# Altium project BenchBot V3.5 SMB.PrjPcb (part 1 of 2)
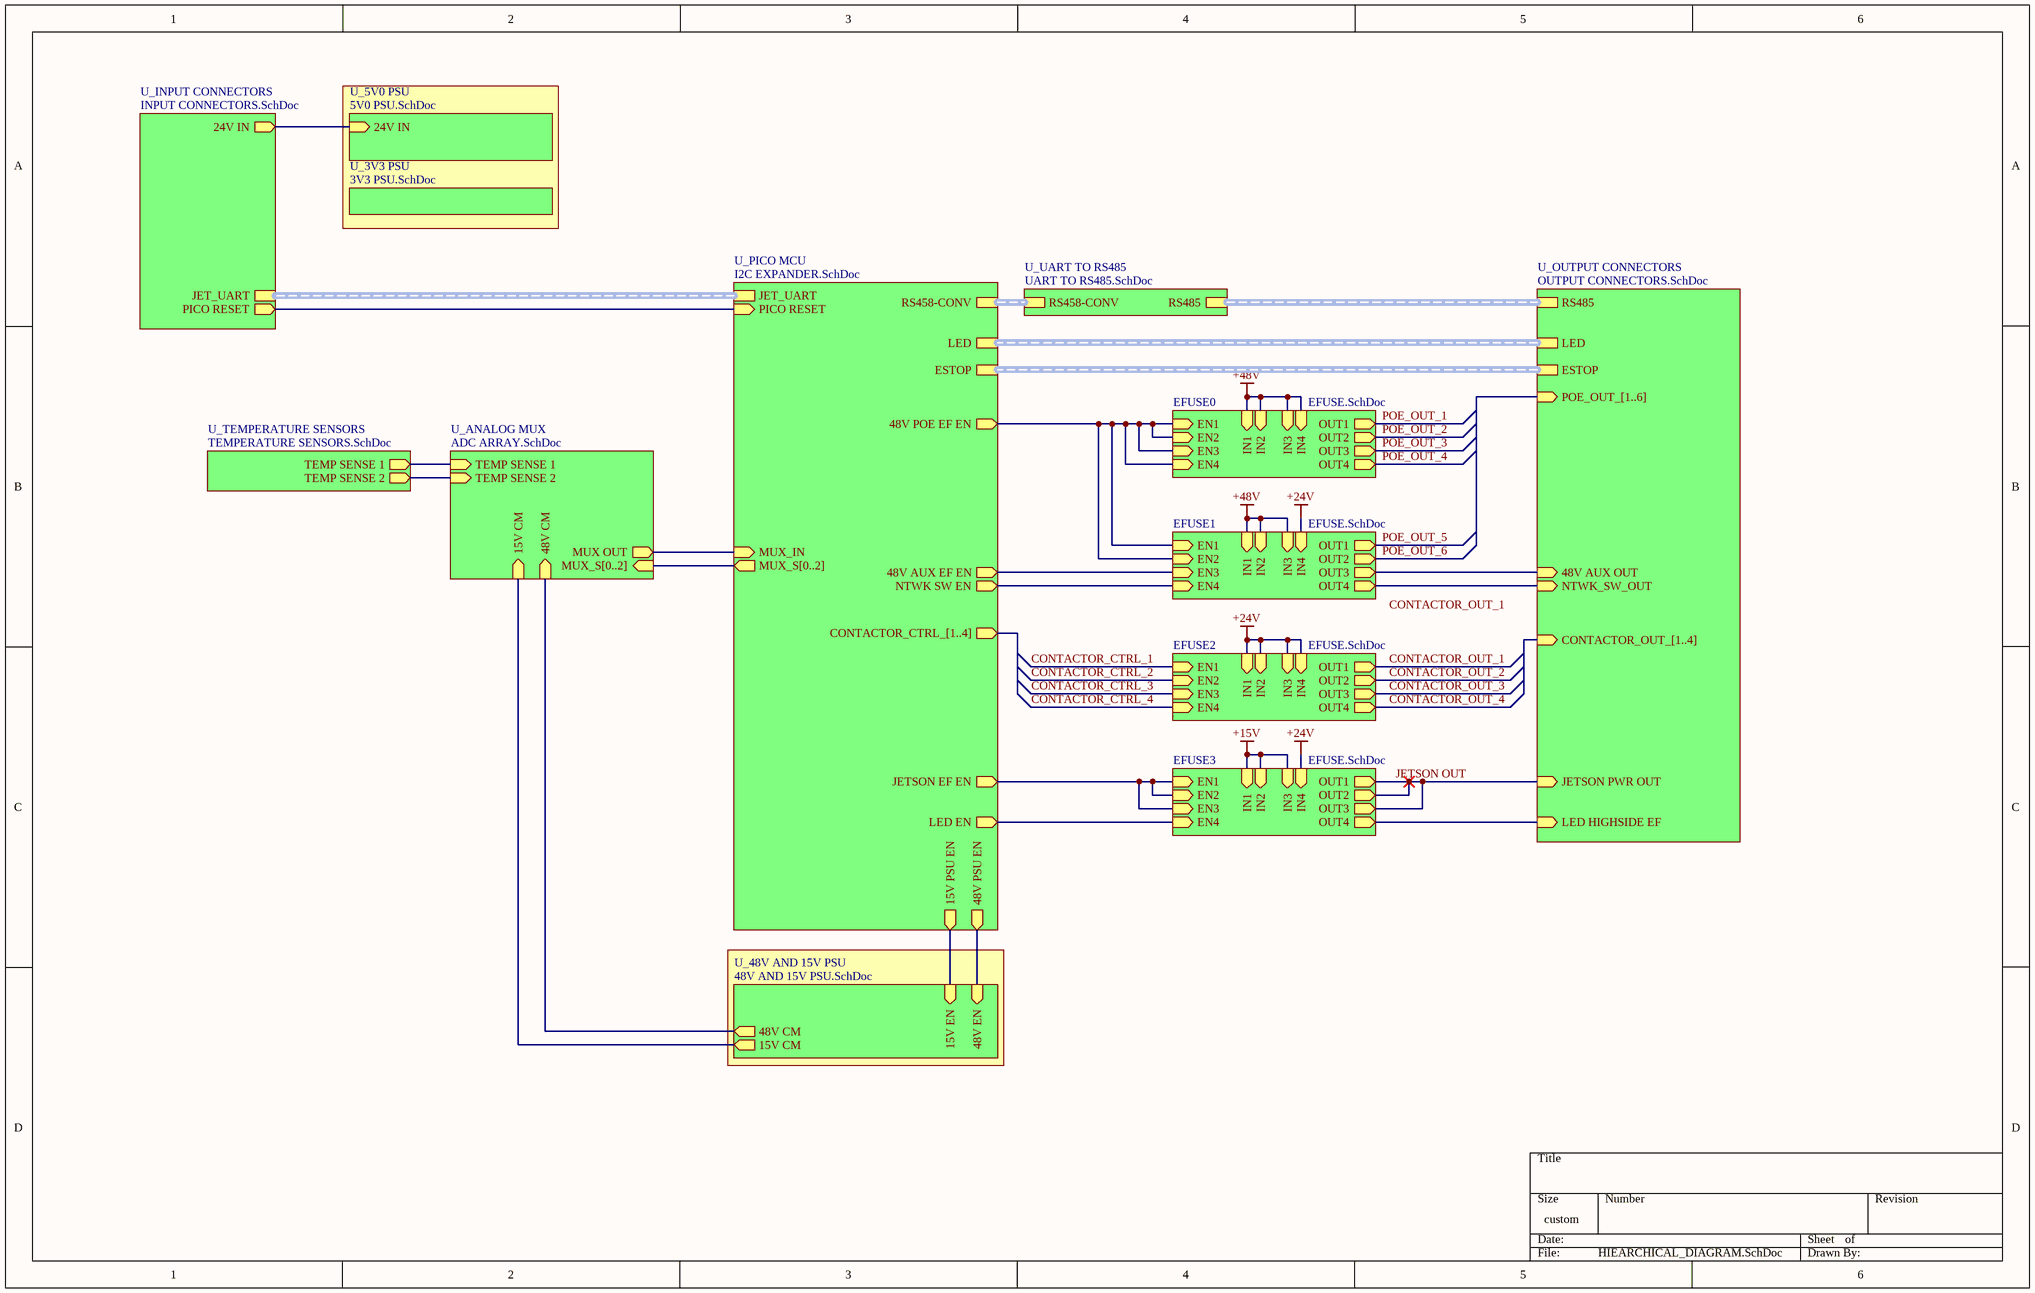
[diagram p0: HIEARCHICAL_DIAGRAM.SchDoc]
13 sheets, 242 parts. Net scope: hierarchical (ports join the sheet entries above them; power ports are global).
Board file: System Management Board.PcbDoc
Sheets:
  HIEARCHICAL_DIAGRAM.SchDoc
    U_3V3 PSU = 3V3 PSU.SchDoc
    U_5V0 PSU = 5V0 PSU.SchDoc
    U_ANALOG MUX = ADC ARRAY.SchDoc
    EFUSE0 = EFUSE.SchDoc
    U_INPUT CONNECTORS = INPUT CONNECTORS.SchDoc
    U_OUTPUT CONNECTORS = OUTPUT CONNECTORS.SchDoc
    U_PICO MCU = I2C EXPANDER.SchDoc
    U_TEMPERATURE SENSORS = TEMPERATURE SENSORS.SchDoc
    U_UART TO RS485 = UART TO RS485.SchDoc
    U_48V AND 15V PSU = 48V AND 15V PSU.SchDoc
    EFUSE1 = EFUSE.SchDoc
    EFUSE2 = EFUSE.SchDoc
    EFUSE3 = EFUSE.SchDoc
  MECHANICAL.SchDoc
  ADC.SchDoc

## Sheet HIEARCHICAL_DIAGRAM.SchDoc
size 381 x 241 mm

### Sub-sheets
EFUSE0 = EFUSE.SchDoc: OUT1 (out), EN1 (in), IN1 (in), IN2 (in), IN3 (in), IN4 (in), OUT2 (out), OUT3 (out), OUT4 (out), EN2 (in), EN3 (in), EN4 (in)
EFUSE1 = EFUSE.SchDoc: OUT1 (out), EN1 (in), IN1 (in), IN2 (in), IN3 (in), IN4 (in), OUT2 (out), OUT3 (out), OUT4 (out), EN2 (in), EN3 (in), EN4 (in)
EFUSE2 = EFUSE.SchDoc: OUT1 (out), EN1 (in), IN1 (in), IN2 (in), IN3 (in), IN4 (in), OUT2 (out), OUT3 (out), OUT4 (out), EN2 (in), EN3 (in), EN4 (in)
EFUSE3 = EFUSE.SchDoc: OUT1 (out), EN1 (in), IN1 (in), IN2 (in), IN3 (in), IN4 (in), OUT2 (out), OUT3 (out), OUT4 (out), EN2 (in), EN3 (in), EN4 (in)
U_3V3 PSU = 3V3 PSU.SchDoc: no entries
U_5V0 PSU = 5V0 PSU.SchDoc: 24V IN (in)
U_48V AND 15V PSU = 48V AND 15V PSU.SchDoc: 48V CM (out), 15V CM (out), 15V EN (in), 48V EN (in)
U_ANALOG MUX = ADC ARRAY.SchDoc: MUX OUT (out), TEMP SENSE 2 (in), TEMP SENSE 1 (in), 48V CM (in), 15V CM (in), MUX_S[0..2] (in)
U_INPUT CONNECTORS = INPUT CONNECTORS.SchDoc: PICO RESET (out), JET_UART (harness UART0), 24V IN (out)
U_OUTPUT CONNECTORS = OUTPUT CONNECTORS.SchDoc: NTWK_SW_OUT (in), JETSON PWR OUT (in), 48V AUX OUT (in), RS485 (harness RS485), LED HIGHSIDE EF (in), CONTACTOR_OUT_[1..4] (in), ESTOP (harness ESTOP_CONN), LED (harness LED), POE_OUT_[1..6] (in)
U_PICO MCU = I2C EXPANDER.SchDoc: NTWK SW EN (out), LED EN (out), ESTOP (harness ESTOP_CONN), JETSON EF EN (out), 15V PSU EN (out), 48V PSU EN (out), RS458-CONV (harness RS485 CONVERSION), JET_UART (harness UART0), CONTACTOR_CTRL_[1..4] (out), PICO RESET (in), MUX_S[0..2] (out), MUX_IN (in), 48V AUX EF EN (out), LED (harness LED), 48V POE EF EN (out)
U_TEMPERATURE SENSORS = TEMPERATURE SENSORS.SchDoc: TEMP SENSE 1 (out), TEMP SENSE 2 (out)
U_UART TO RS485 = UART TO RS485.SchDoc: RS485 (harness RS485), RS458-CONV (harness RS485 CONVERSION)

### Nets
+15V: sheet EFUSE3/IN1, sheet EFUSE3/IN2, sheet EFUSE3/IN3
+24V: sheet EFUSE1/IN4, sheet EFUSE2/IN1, sheet EFUSE2/IN2, sheet EFUSE2/IN3, sheet EFUSE2/IN4, sheet EFUSE3/IN4
+48V: sheet EFUSE0/IN1, sheet EFUSE0/IN2, sheet EFUSE0/IN3, sheet EFUSE0/IN4, sheet EFUSE1/IN1, sheet EFUSE1/IN2, sheet EFUSE1/IN3
15V CM: sheet U_ANALOG MUX/15V CM, sheet U_48V AND 15V PSU/15V CM
48V POE EF EN: sheet EFUSE0/EN1, sheet EFUSE0/EN2, sheet EFUSE0/EN3, sheet EFUSE0/EN4, sheet U_PICO MCU/48V POE EF EN, sheet EFUSE1/EN1, sheet EFUSE1/EN2
48V_AUX_EF_EN: sheet U_PICO MCU/48V AUX EF EN, sheet EFUSE1/EN3
+24_VIN: sheet U_5V0 PSU/24V IN, sheet U_INPUT CONNECTORS/24V IN
~{+15_PWR_EN}: sheet U_PICO MCU/15V PSU EN, sheet U_48V AND 15V PSU/15V EN
~{+48_PWR_EN}: sheet U_PICO MCU/48V PSU EN, sheet U_48V AND 15V PSU/48V EN
EN1: sheet U_PICO MCU/JETSON EF EN, sheet EFUSE3/EN1, sheet EFUSE3/EN2, sheet EFUSE3/EN3
EN4: sheet U_PICO MCU/NTWK SW EN, sheet EFUSE1/EN4
EN4: sheet U_PICO MCU/LED EN, sheet EFUSE3/EN4  [a separate net that carries the same name]
JETSON OUT: sheet U_OUTPUT CONNECTORS/JETSON PWR OUT, sheet EFUSE3/OUT1, sheet EFUSE3/OUT2, sheet EFUSE3/OUT3
MUX OUT: sheet U_ANALOG MUX/MUX OUT, sheet U_PICO MCU/MUX_IN
OUT3: sheet U_OUTPUT CONNECTORS/48V AUX OUT, sheet EFUSE1/OUT3
OUT4: sheet U_OUTPUT CONNECTORS/NTWK_SW_OUT, sheet EFUSE1/OUT4
OUT4: sheet U_OUTPUT CONNECTORS/LED HIGHSIDE EF, sheet EFUSE3/OUT4  [a separate net that carries the same name]
POE SW PWR CM: sheet U_ANALOG MUX/48V CM, sheet U_48V AND 15V PSU/48V CM
TEMP SENSE 1: sheet U_ANALOG MUX/TEMP SENSE 1, sheet U_TEMPERATURE SENSORS/TEMP SENSE 1
TEMP SENSE 2: sheet U_ANALOG MUX/TEMP SENSE 2, sheet U_TEMPERATURE SENSORS/TEMP SENSE 2
(unnamed): sheet U_INPUT CONNECTORS/PICO RESET, sheet U_PICO MCU/PICO RESET

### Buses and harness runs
bus sheet U_ANALOG MUX/MUX_S[0..2] = sheet U_PICO MCU/MUX_S[0..2]
harness sheet U_INPUT CONNECTORS/JET_UART = sheet U_PICO MCU/JET_UART
harness sheet U_OUTPUT CONNECTORS/ESTOP = sheet U_PICO MCU/ESTOP
harness sheet U_OUTPUT CONNECTORS/LED = sheet U_PICO MCU/LED
harness sheet U_OUTPUT CONNECTORS/RS485 = sheet U_UART TO RS485/RS485
harness sheet U_PICO MCU/RS458-CONV = sheet U_UART TO RS485/RS458-CONV

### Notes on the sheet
- Labels drawn without touching a wire or pin: CONTACTOR_OUT_1

## Sheet 3V3 PSU.SchDoc
size A
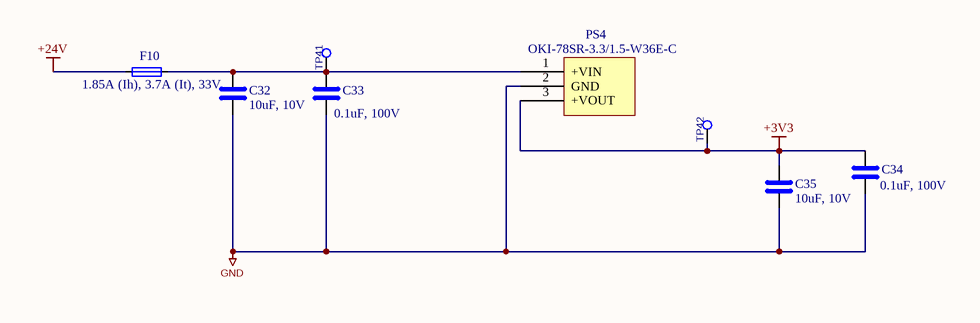
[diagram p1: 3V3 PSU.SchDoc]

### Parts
C32  Parameter 1: 10uF, 10V  [C_0805]  (hidden comment: CL21B106KPQNFNE)
C33  Parameter 1: 0.1uF, 100V  [C_0603]  (hidden comment: CL10B104KC8NNNC)
C34  Parameter 1: 0.1uF, 100V  [C_0603]  (hidden comment: CL10B104KC8NNNC)
C35  Parameter 1: 10uF, 10V  [C_0805]  (hidden comment: CL21B106KPQNFNE)
F10  Parameter 1: 1.85A (Ih), 3.7A (It), 33V  [0ZCF]  (hidden comment: 0ZCF0185FF2C)
PS4  OKI-78SR-3.3/1.5-W36E-C  [OKI-78SR-5&slash_1.5-W36E-C]
TP41  Comment  [TestPoint_Pad_D1.0mm]  (value not drawn)
TP42  Comment  [TestPoint_Pad_D1.0mm]  (value not drawn)

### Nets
+3V3: C34.1 C35.1 PS4.3(+VOUT) TP42.1
+24V: F10.1
GND: C32.2 C33.2 C34.2 C35.2 PS4.2(GND)
NetC32_1: C32.1 C33.1 F10.2 PS4.1(+VIN) TP41.1

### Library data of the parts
C32 C35 = CL21B106KPQNFNE: Ceramic Capacitor, Multilayer, Ceramic, 10V, 10% +Tol, 10% -Tol, X7R, 15% TC, 10uF, Surface Mount, 0805; Manufacturer: Samsung; Multilayer: Yes
C33 C34 = CL10B104KC8NNNC: Ceramic Capacitor, Multilayer, Ceramic, 100V, 10% +Tol, 10% -Tol, X7R, 15% TC, 0.1uF, Surface Mount, 0603; Manufacturer: Samsung; Multilayer: Yes; Value: 100nF
F10 = 0ZCF0185FF2C: PTC Resettable Fuse, 33V, 0.04ohm, Surface Mount; Manufacturer: Bel; Power: 1.5W; Thermistor Application: TEMPERATURE SENSING
PS4 = OKI-78SR-3.3/1.5-W36E-C: DC-DC Regulated Power Supply Module, 1 Output, 5.15W, Hybrid; Manufacturer: Murata; Max Supply Voltage: 36V; Min Input Voltage: 7V; Nominal Supply Voltage: 12V; Load Regulation-Max: 0.4%; Channels: 1; Max Output Voltage: 3.432V; Min Output Voltage: 3.168V; Nominal Output Voltage: 3.3V; Surface Mount: No; Trim/Adjustable Output: No
TP41 TP42 = TestPoint_1: Value: KeySwitch IN

## Sheet 5V0 PSU.SchDoc
size A
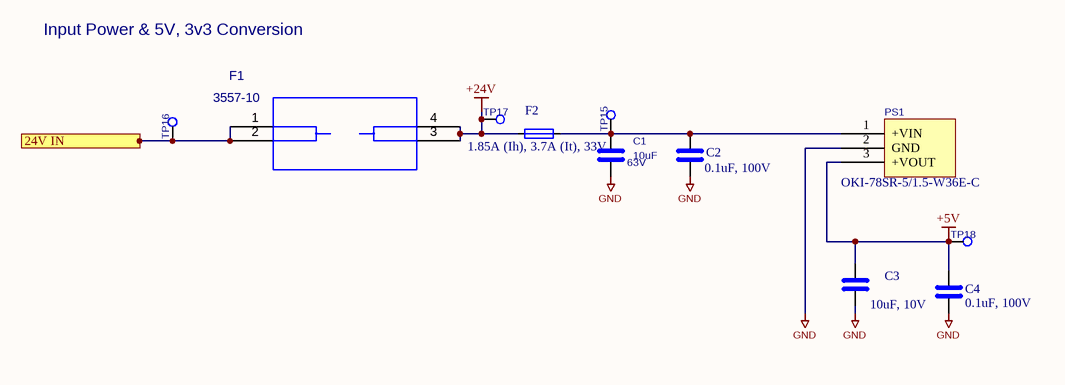
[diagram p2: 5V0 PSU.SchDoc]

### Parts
C1  value 10uF  Voltage: 63V  [C_1210_3225Metric]  (hidden comment: C)
C2  Parameter 1: 0.1uF, 100V  [C_0603]  (hidden comment: CL10B104KC8NNNC)
C3  Parameter 1: 10uF, 10V  [C_0805]  (hidden comment: CL21B106KPQNFNE)
C4  Parameter 1: 0.1uF, 100V  [C_0603]  (hidden comment: CL10B104KC8NNNC)
F1  value 3557-10  [3557-10]  (hidden comment: Comment)
F2  Parameter 1: 1.85A (Ih), 3.7A (It), 33V  [0ZCF]  (hidden comment: 0ZCF0185FF2C)
PS1  OKI-78SR-5/1.5-W36E-C  [OKI-78SR-5&slash_1.5-W36E-C]
TP15  Comment  [TestPoint_Pad_D1.0mm]  (value not drawn)
TP16  Comment  [TestPoint_Pad_D1.0mm]  (value not drawn)
TP17  Comment  [TestPoint_Pad_D1.0mm]  (value not drawn)
TP18  Comment  [TestPoint_Pad_D1.0mm]  (value not drawn)

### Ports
24V IN (in)

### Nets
+5V: C3.1 C4.1 PS1.3(+VOUT) TP18.1
+24V: F1.3 F1.4 F2.1 TP17.1
GND: C1.2 C2.2 C3.2 C4.2 PS1.2(GND)
+24_VIN: F1.1 F1.2 TP16.1 ; port 24V IN
NetC1_1: C1.1 C2.1 F2.2 PS1.1(+VIN) TP15.1

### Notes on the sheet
- Input Power & 5V, 3v3 Conversion

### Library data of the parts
C1 = C: Ceramic Capacitor, Multilayer, Ceramic, 63V, 10% +Tol, 10% -Tol, X7R, 15% TC, 10uF, Surface Mount, 1210; Manufacturer: Samsung; Manufacturer Part Number: CL32B106KMVNNWE; Multilayer: Yes
C2 C4 = CL10B104KC8NNNC: as C33 on sheet 3V3 PSU
C3 = CL21B106KPQNFNE: as C32 on sheet 3V3 PSU
F1 = 3557-10: Holder; Fuse; Auto Blade; 30A; PC Pin Terminal; Nylon Holder; Red; Manufacturer: Keystone Electronics
F2 = 0ZCF0185FF2C: as F10 on sheet 3V3 PSU
PS1 = OKI-78SR-5/1.5-W36E-C: DC-DC Regulated Power Supply Module, 1 Output, 7.8W, Hybrid; Manufacturer: Murata; Max Supply Voltage: 36V; Min Input Voltage: 7V; Nominal Supply Voltage: 12V; Load Regulation-Max: 0.4%; Channels: 1; Max Output Voltage: 5.2V; Min Output Voltage: 4.8V; Nominal Output Voltage: 5V; Surface Mount: No; Trim/Adjustable Output: No
TP15-TP18 = TestPoint_1: Value: KeySwitch IN

## Sheet ADC ARRAY.SchDoc
size A
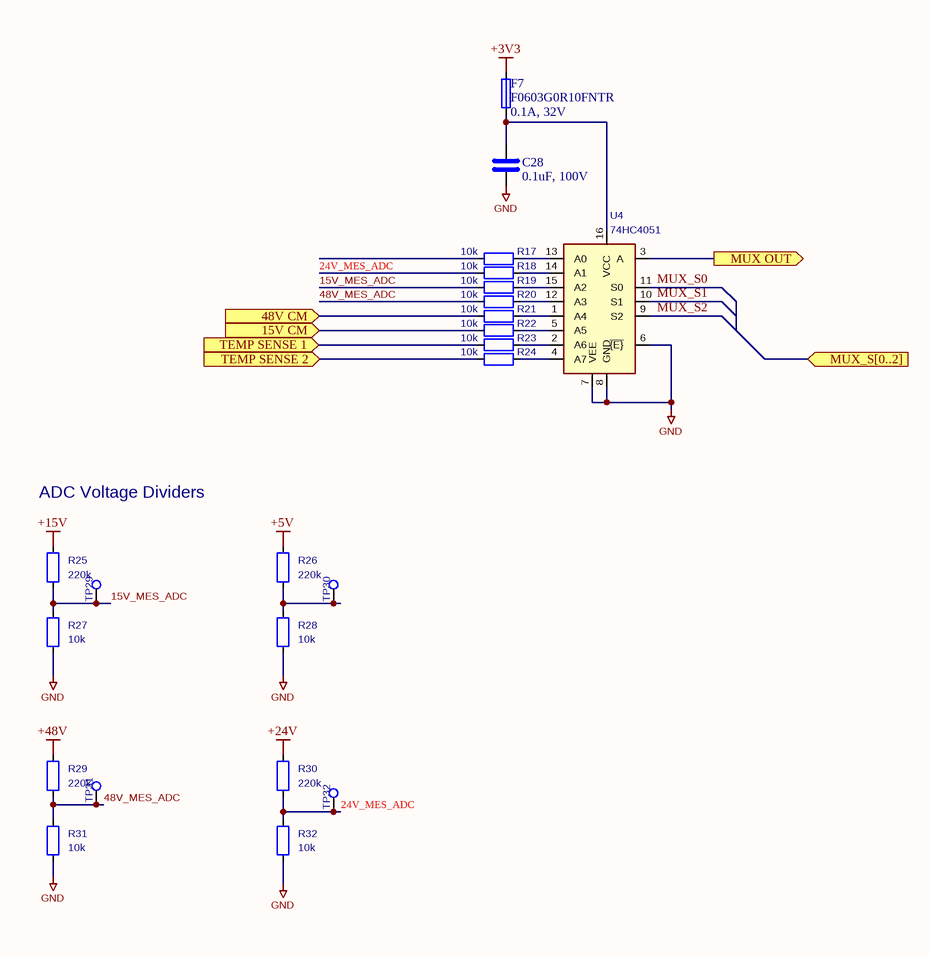
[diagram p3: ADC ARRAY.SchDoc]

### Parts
C28  Parameter 1: 0.1uF, 100V  [C_0603]  (hidden comment: CL10B104KC8NNNC)
F7  F0603G0R10FNTR  Parameter 1: 0.1A, 32V  [FUSE_0603]
R17  value 10k  [R_1206_3216Metric]  (hidden comment: Comment)
R18  value 10k  [R_1206_3216Metric]  (hidden comment: Comment)
R19  value 10k  [R_1206_3216Metric]  (hidden comment: Comment)
R20  value 10k  [R_1206_3216Metric]  (hidden comment: Comment)
R21  value 10k  [R_1206_3216Metric]  (hidden comment: Comment)
R22  value 10k  [R_1206_3216Metric]  (hidden comment: Comment)
R23  value 10k  [R_1206_3216Metric]  (hidden comment: Comment)
R24  value 10k  [R_1206_3216Metric]  (hidden comment: Comment)
R25  value 220k  [R_1206_3216Metric]  (hidden comment: Comment)
R26  value 220k  [R_1206_3216Metric]  (hidden comment: Comment)
R27  value 10k  [R_1206_3216Metric]  (hidden comment: Comment)
R28  value 10k  [R_1206_3216Metric]  (hidden comment: Comment)
R29  value 220k  [R_1206_3216Metric]  (hidden comment: Comment)
R30  value 220k  [R_1206_3216Metric]  (hidden comment: Comment)
R31  value 10k  [R_1206_3216Metric]  (hidden comment: Comment)
R32  value 10k  [R_1206_3216Metric]  (hidden comment: Comment)
TP29  Comment  [TestPoint_Pad_D1.0mm]  (value not drawn)
TP30  Comment  [TestPoint_Pad_D1.0mm]  (value not drawn)
TP31  Comment  [TestPoint_Pad_D1.0mm]  (value not drawn)
TP32  Comment  [TestPoint_Pad_D1.0mm]  (value not drawn)
U4  value 74HC4051  [TSSOP-16_4.4x5mm_P0.65mm]  (hidden comment: Comment)

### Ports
15V CM (in), 48V CM (in), MUX OUT (out), MUX_S[0..2] (in), TEMP SENSE 1 (in), TEMP SENSE 2 (in)

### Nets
+3V3: F7.1
+5V: R26.2
+15V: R25.2
+24V: R30.2
+48V: R29.2
GND: C28.2 R27.2 R28.2 R31.2 R32.2 U4.6(~{{E}}) U4.7(VEE) U4.8(GND)
15V CM: R22.1 ; port 15V CM
15V_MES_ADC: R19.1 R25.1 R27.1 TP29.1
24V_MES_ADC: R18.1 R30.1 R32.1 TP32.1
48V_MES_ADC: R20.1 R29.1 R31.1 TP31.1
MUX OUT: U4.3(A) ; port MUX OUT
MUX_S0: U4.11(S0)
MUX_S1: U4.10(S1)
MUX_S2: U4.9(S2)
POE SW PWR CM: R21.1 ; port 48V CM
TEMP SENSE 1: R23.1 ; port TEMP SENSE 1
TEMP SENSE 2: R24.1 ; port TEMP SENSE 2
NetC28_1: C28.1 F7.2 U4.16(VCC)
NetR17_2: R17.2 U4.13(A0)
NetR18_2: R18.2 U4.14(A1)
NetR19_2: R19.2 U4.15(A2)
NetR20_2: R20.2 U4.12(A3)
NetR21_2: R21.2 U4.1(A4)
NetR22_2: R22.2 U4.5(A5)
NetR23_2: R23.2 U4.2(A6)
NetR24_2: R24.2 U4.4(A7)
NetR26_1: R26.1 R28.1 TP30.1

Not connected (* = marked no-connect by the designer): R17 1

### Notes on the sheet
- (near R25) ADC Voltage Dividers

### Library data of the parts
C28 = CL10B104KC8NNNC: as C33 on sheet 3V3 PSU
F7 = F0603G0R10FNTR: Electric Fuse, Fast Blow, 0.1A, 32VAC, 32VDC, Surface Mount; Manufacturer: Kyocera AVX; Joule-integral-Nom: 7E-06J; Current Rating: 100mA; Body Breadth: 0.81mm; Body Height: 0.61mm; Body Length or Diameter: 1.6mm; Reference Standard: UL
R17-R32 = R
TP29-TP32 = TestPoint_1: Value: KeySwitch IN
U4 = 74HC4051

## Sheet EFUSE.SchDoc
size A
Used 4 times, as channels EFUSE0, EFUSE1, EFUSE2, EFUSE3. Parts and nets are listed once, with the designators drawn on the sheet.
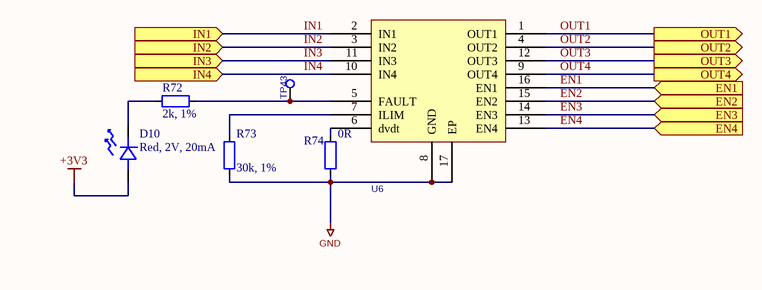
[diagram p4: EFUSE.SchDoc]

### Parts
D10  Parameter 1: Red, 2V, 20mA  [LED_0603]  (hidden comment: B1931USD-20D000814U1930)
R72  Parameter 1: 2k, 1%  [C_0603]  (hidden comment: RMCF0603FT2K00)
R73  Parameter 1: 30k, 1%  [R_0603]  (hidden comment: RMCF0603FT30K0)
R74  Parameter 1: 0R  [R_0603]  (hidden comment: RMCF0603ZT0R00)
TP43  Comment  [TestPoint_Pad_D1.0mm]  (value not drawn)
U6  NIV3071MTW3TWG  [16-WQFN-5x6]  (value not drawn)

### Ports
EN1 (in), EN2 (in), EN3 (in), EN4 (in), IN1 (in), IN2 (in), IN3 (in), IN4 (in), OUT1 (out), OUT2 (out), OUT3 (out), OUT4 (out)

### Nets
+3V3: D10.1
GND: R73.2 R74.2 U6.8(GND) U6.17(EP)
EN1: U6.16(EN1) ; port EN1
EN2: U6.15(EN2) ; port EN2
EN3: U6.14(EN3) ; port EN3
EN4: U6.13(EN4) ; port EN4
IN1: U6.2(IN1) ; port IN1
IN2: U6.3(IN2) ; port IN2
IN3: U6.11(IN3) ; port IN3
IN4: U6.10(IN4) ; port IN4
OUT1: U6.1(OUT1) ; port OUT1
OUT2: U6.4(OUT2) ; port OUT2
OUT3: U6.12(OUT3) ; port OUT3
OUT4: U6.9(OUT4) ; port OUT4
NetD10_2: D10.2 R72.1
NetR72_2: R72.2 TP43.1 U6.5(FAULT)
NetR73_1: R73.1 U6.7(ILIM)
NetR74_1: R74.1 U6.6(dvdt)

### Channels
EFUSE0: designators end in _EFUSE0; ports EN1=48V POE EF EN EN2=48V POE EF EN EN3=48V POE EF EN EN4=48V POE EF EN IN1=+48V IN2=+48V IN3=+48V IN4=+48V OUT1=POE_OUT_1 OUT2=POE_OUT_2 OUT3=POE_OUT_3 OUT4=POE_OUT_4
EFUSE1: designators end in _EFUSE1; ports EN1=48V POE EF EN EN2=48V POE EF EN EN3=48V_AUX_EF_EN EN4=EN4 IN1=+48V IN2=+48V IN3=+48V IN4=+24V OUT1=POE_OUT_5 OUT2=POE_OUT_6 OUT3=OUT3 OUT4=OUT4
EFUSE2: designators end in _EFUSE2; ports EN1=CONTACTOR_CTRL_1 EN2=CONTACTOR_CTRL_2 EN3=CONTACTOR_CTRL_3 EN4=CONTACTOR_CTRL_4 IN1=+24V IN2=+24V IN3=+24V IN4=+24V OUT1=CONTACTOR_OUT_1 OUT2=CONTACTOR_OUT_2 OUT3=CONTACTOR_OUT_3 OUT4=CONTACTOR_OUT_4
EFUSE3: designators end in _EFUSE3; ports EN1=EN1 EN2=EN1 EN3=EN1 EN4=EN4 IN1=+15V IN2=+15V IN3=+15V IN4=+24V OUT1=JETSON OUT OUT2=JETSON OUT OUT3=JETSON OUT OUT4=OUT4

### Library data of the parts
D10 = B1931USD-20D000814U1930: Led Red Diffused 0603 SMD; Manufacturer: Inolux
R72 = RMCF0603FT2K00: Fixed Resistor, Metal Glaze/thick Film, 0.1W, 2000ohm, 75V, 1% +/-Tol, 100ppm/Cel, Surface Mount, 0603; Manufacturer: Stackpole Electronics; Power: 100mW; Rated Temperature: 70°C; Value: 2kR; Temperature Coefficient (ppm/Cel): 100; Package Height: 0.45mm; Package Length: 1.55mm; Package Width: 0.8mm; Reference Standard: AEC-Q200
R73 = RMCF0603FT30K0: Fixed Resistor, Metal Glaze/thick Film, 0.1W, 30000ohm, 75V, 1% +/-Tol, 100ppm/Cel, Surface Mount, 0603; Manufacturer: Stackpole Electronics; Power: 100mW; Rated Temperature: 70°C; Value: 30kR; Temperature Coefficient (ppm/Cel): 100; Package Height: 0.45mm; Package Length: 1.55mm; Package Width: 0.8mm; Reference Standard: AEC-Q200
R74 = RMCF0603ZT0R00: Fixed Resistor, Metal Glaze/thick Film, 0.1W, 0ohm, Surface Mount, 0603; Manufacturer: Stackpole Electronics; Power: 100mW; Rated Temperature: 70°C; Value: 0R; Working Voltage: 75V; Package Height: 0.45mm; Package Length: 1.55mm; Package Width: 0.8mm; Reference Standard: AEC-Q200
TP43 = TestPoint_1: Value: KeySwitch IN
U6 = NIV3071MTW3TWG: Electronic fuse (eFuse) 4-channel, 8V to 60V, 10A in 5x6mm package Latch version; Manufacturer: onsemi

## Sheet INPUT CONNECTORS.SchDoc
size A
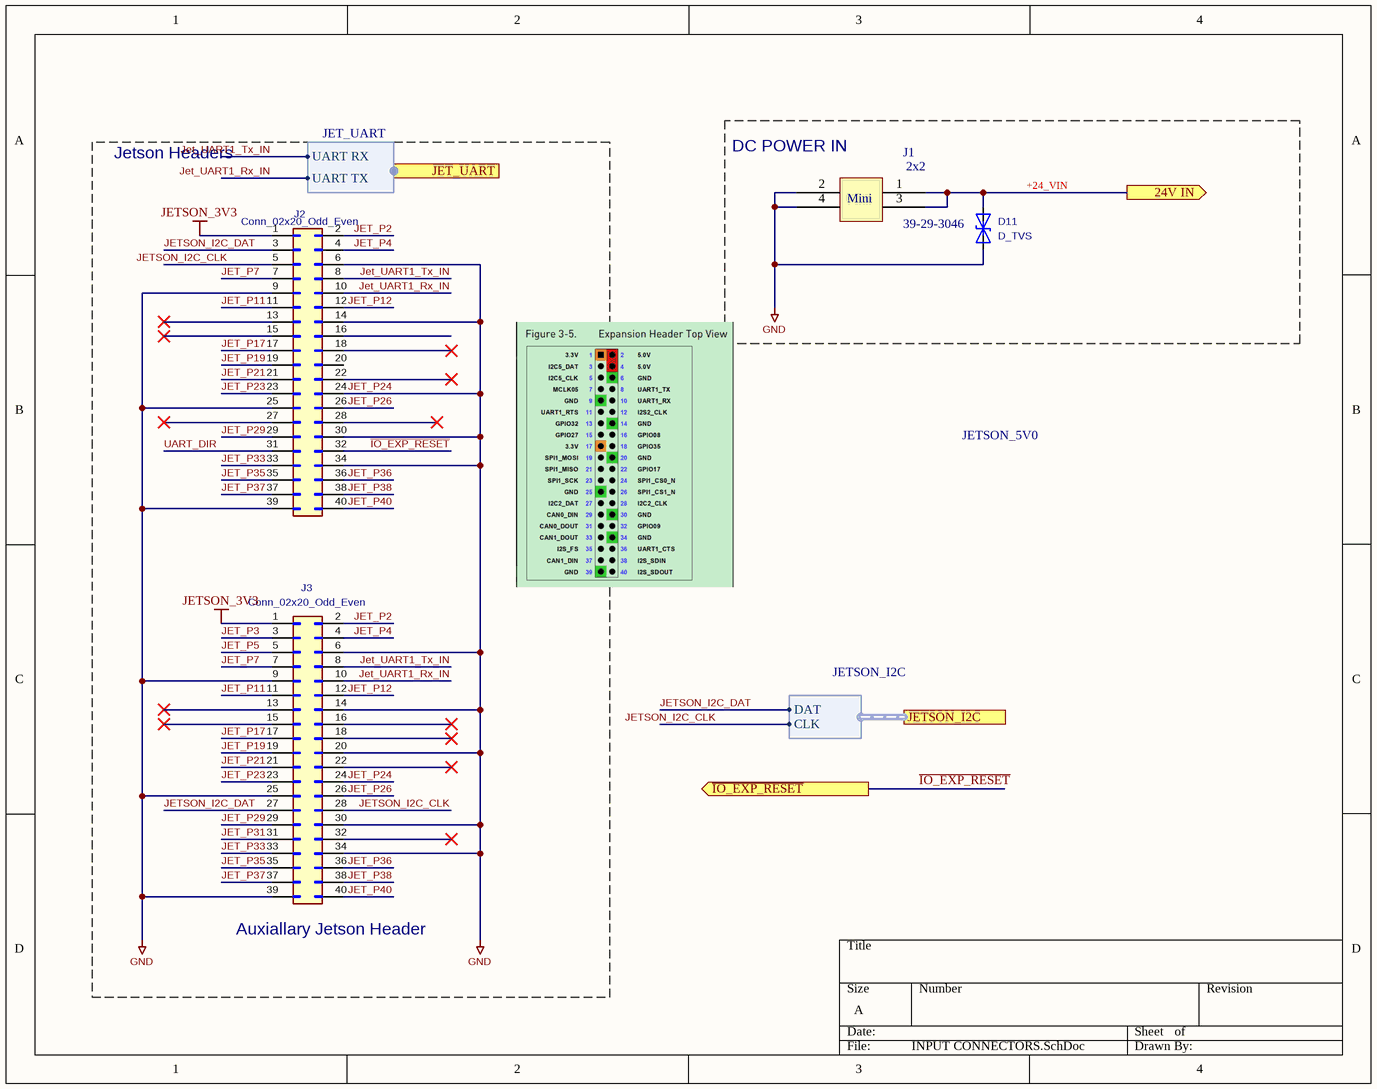
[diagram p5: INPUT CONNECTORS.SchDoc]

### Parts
D11  D_TVS  [D_SMA]
J1  39-29-3046  Parameter 1: 2x2  Parameter 2: Mini  [39-29-3046]
J2  value Conn_02x20_Odd_Even  [PinHeader_2x20_P2.54mm_Horizontal]  (hidden comment: Comment)
J3  value Conn_02x20_Odd_Even  [PinHeader_2x20_P2.54mm_Vertical]  (hidden comment: Comment)

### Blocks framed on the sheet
DC POWER IN: D11 J1

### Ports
24V IN (out), JET_UART (harness JET_UART), JETSON_I2C (harness JETSON_I2C), ~{IO_EXP_RESET} (out)

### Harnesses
JET_UART: UART RX, UART TX
JETSON_I2C: DAT, CLK

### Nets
GND: D11.1(A1) J1.2 J1.4 J2.6(Pin_6) J2.9(Pin_9) J2.14(Pin_14) J2.24(Pin_24) J2.25(Pin_25) J2.30(Pin_30) J2.34(Pin_34) J2.39(Pin_39) J3.6(Pin_6) J3.9(Pin_9) J3.14(Pin_14) J3.20(Pin_20) J3.24(Pin_24) J3.25(Pin_25) J3.30(Pin_30) J3.34(Pin_34) J3.39(Pin_39)  [also labelled JET_P24]
JETSON_3V3: J2.1(Pin_1) J3.1(Pin_1)
+24_VIN: D11.2(A2) J1.1 J1.3 ; port 24V IN
~{IO_EXP_RESET}: J2.32(Pin_32) ; port ~{IO_EXP_RESET}
JET_P2: J2.2(Pin_2) J3.2(Pin_2)
JET_P3: J3.3(Pin_3)
JET_P4: J2.4(Pin_4) J3.4(Pin_4)
JET_P5: J3.5(Pin_5)
JET_P7: J2.7(Pin_7) J3.7(Pin_7)
JET_P11: J2.11(Pin_11) J3.11(Pin_11)
JET_P12: J2.12(Pin_12) J3.12(Pin_12)
JET_P17: J2.17(Pin_17) J3.17(Pin_17)
JET_P19: J2.19(Pin_19) J3.19(Pin_19)
JET_P21: J2.21(Pin_21) J3.21(Pin_21)
JET_P23: J2.23(Pin_23) J3.23(Pin_23)
JET_P26: J2.26(Pin_26) J3.26(Pin_26)
JET_P29: J2.29(Pin_29) J3.29(Pin_29)
JET_P31: J3.31(Pin_31)
JET_P33: J2.33(Pin_33) J3.33(Pin_33)
JET_P35: J2.35(Pin_35) J3.35(Pin_35)
JET_P36: J2.36(Pin_36) J3.36(Pin_36)
JET_P37: J2.37(Pin_37) J3.37(Pin_37)
JET_P38: J2.38(Pin_38) J3.38(Pin_38)
JET_P40: J2.40(Pin_40) J3.40(Pin_40)
Jet_UART1_Rx_IN: J2.10(Pin_10) J3.10(Pin_10) ; port JET_UART.UART TX
Jet_UART1_Tx_IN: J2.8(Pin_8) J3.8(Pin_8) ; port JET_UART.UART RX  [project net Jet_UART1_Rx]
JETSON_I2C_CLK: J2.5(Pin_5) J3.28(Pin_28) ; port JETSON_I2C.CLK
JETSON_I2C_DAT: J2.3(Pin_3) J3.27(Pin_27) ; port JETSON_I2C.DAT
UART_DIR: J2.31(Pin_31)

Not connected (* = marked no-connect by the designer): J2 13(Pin_13)* 15(Pin_15)* 16(Pin_16) 18(Pin_18)* 20(Pin_20) 22(Pin_22)* 27(Pin_27)* 28(Pin_28)*; J3 13(Pin_13)* 15(Pin_15)* 16(Pin_16)* 18(Pin_18)* 22(Pin_22)* 32(Pin_32)*

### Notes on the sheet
- Jetson Headers
- JETSON_5V0
- (near J3) Auxiallary Jetson Header

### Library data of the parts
J1 = 39-29-3046: Rectangular Power Connector, 4 Contact(s), Male, Solder Terminal, Plug; Manufacturer: Molex; Connector Type: Power,Rectangular; Option: General Purpose; Contact Resistance: 10mR; Contact Style: SQ PIN-SKT; Dielectric Withstanding Voltage (AC): 1.5kV; Durability: 30Cycles; Empty Shell: No; Insertion Force-Max: 6.672N; Insulation Resistance: 1GR; Mating Information: MULTIPLE MATING PARTS AVAILABLE; Number Of Connectors: 1; Number Of PCB Rows: 2; Polarization Key: POLARIZED HOUSING; Rated Current (Signal): 8A; Number of Contacts: 4; Withdrawl Force-Min: 3.1136N; Body Breadth: 0.378inch; Body Depth: 0.504inch; Body Length: 0.38inch; Mating Contact Pitch: 0.165inch; Mounting Option 1: POLARIZED LCK; Mounting Option 2: LOCKING; PCB Contact Row Spacing: 5.5118mm; Plating Thickness: 35uin; Reference Standard: UL; Reliability: COMMERCIAL
J2 J3 = Conn_02x20_Odd_Even

## Sheet OUTPUT CONNECTORS.SchDoc
size 381 x 241 mm
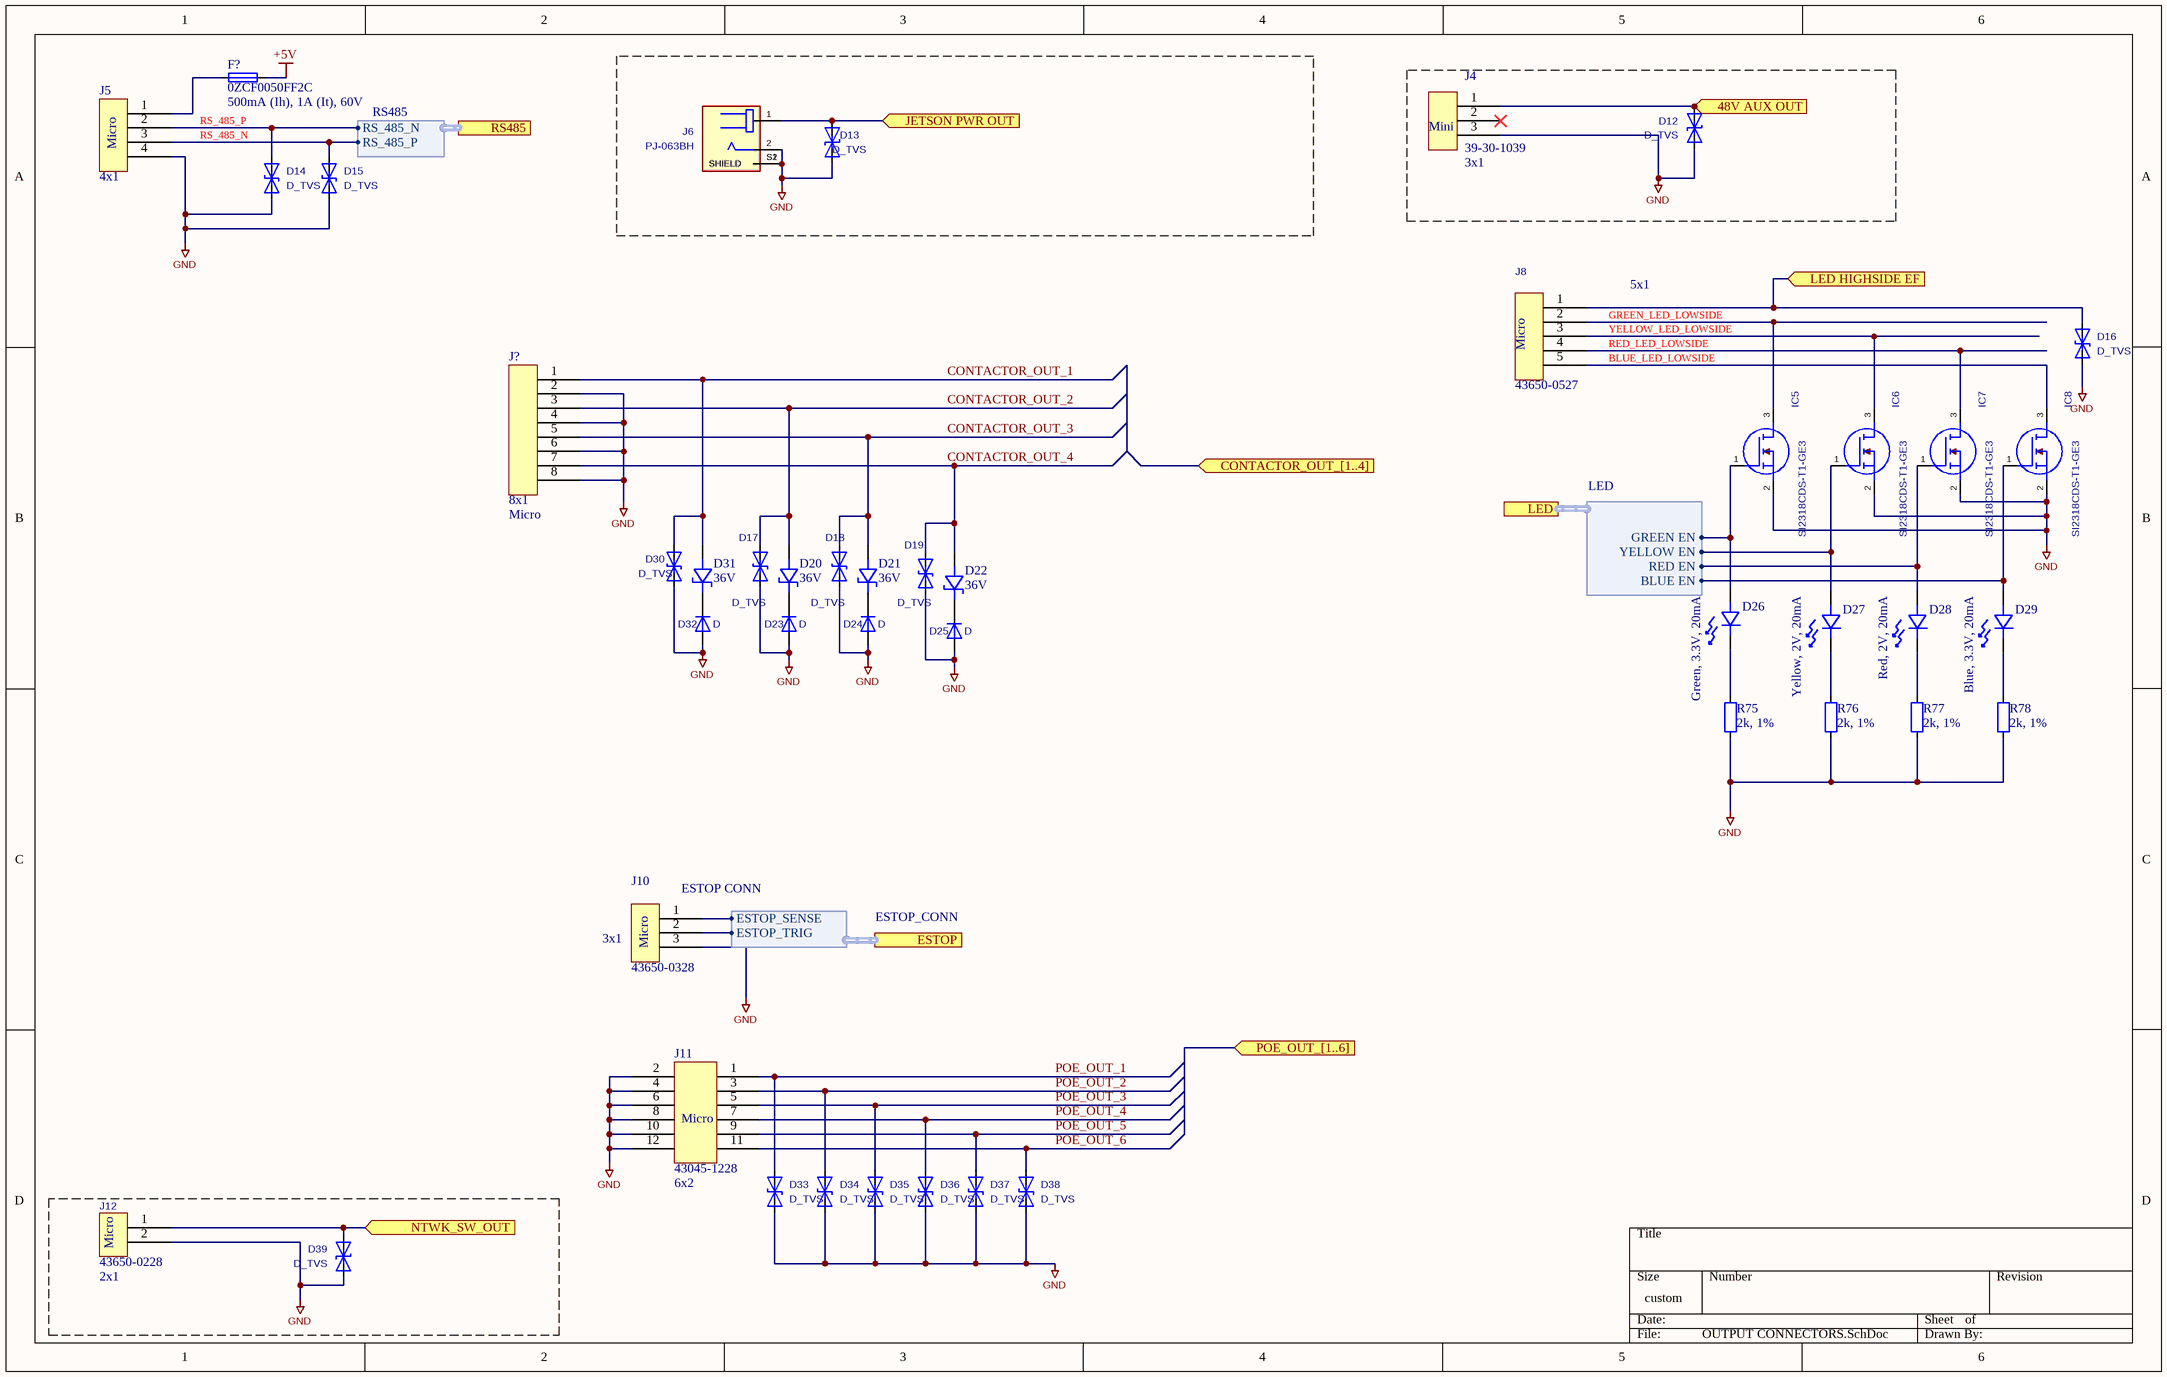
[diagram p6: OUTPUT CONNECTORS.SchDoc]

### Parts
D12  value D_TVS  [D_SMA]  (hidden comment: Comment)
D13  value D_TVS  [D_SMA]  (hidden comment: Comment)
D14  value D_TVS  [D_SMA]  (hidden comment: Comment)
D15  value D_TVS  [D_SMA]  (hidden comment: Comment)
D16  value D_TVS  [D_SMA]  (hidden comment: Comment)
D17  value D_TVS  [D_SMA]  (hidden comment: Comment)
D18  value D_TVS  [D_SMA]  (hidden comment: Comment)
D19  value D_TVS  [D_SMA]  (hidden comment: Comment)
D20  Parameter 1: 36V  [SMAZ36-13-F]  (hidden comment: SMAZ36-13-F)
D21  Parameter 1: 36V  [SMAZ36-13-F]  (hidden comment: SMAZ36-13-F)
D22  Parameter 1: 36V  [SMAZ36-13-F]  (hidden comment: SMAZ36-13-F)
D23  value D  [D_SOD-123F]  (hidden comment: Comment)
D24  value D  [D_SOD-123F]  (hidden comment: Comment)
D25  value D  [D_SOD-123F]  (hidden comment: Comment)
D26  Parameter 1: Green, 3.3V, 20mA  [LED_0603]  (hidden comment: B1931NG--20D001114U1930)
D27  Parameter 1: Yellow, 2V, 20mA  [LED_0603]  (hidden comment: B1931UY--20D000114U1930)
D28  Parameter 1: Red, 2V, 20mA  [LED_0603]  (hidden comment: B1931USD-20D000814U1930)
D29  Parameter 1: Blue, 3.3V, 20mA  [LED_0603]  (hidden comment: B1931NB--20C007614U1930)
D30  value D_TVS  [D_SMA]  (hidden comment: Comment)
D31  Parameter 1: 36V  [SMAZ36-13-F]  (hidden comment: SMAZ36-13-F)
D32  value D  [D_SOD-123F]  (hidden comment: Comment)
D33  value D_TVS  [D_SMA]  (hidden comment: Comment)
D34  value D_TVS  [D_SMA]  (hidden comment: Comment)
D35  value D_TVS  [D_SMA]  (hidden comment: Comment)
D36  value D_TVS  [D_SMA]  (hidden comment: Comment)
D37  value D_TVS  [D_SMA]  (hidden comment: Comment)
D38  value D_TVS  [D_SMA]  (hidden comment: Comment)
D39  value D_TVS  [D_SMA]  (hidden comment: Comment)
F?  0ZCF0050FF2C  Parameter 1: 500mA (Ih), 1A (It), 60V  [0ZCF]
IC5  value SI2318CDS-T1-GE3  [SOT95P237X112-3N]  (hidden comment: Comment)
IC6  value SI2318CDS-T1-GE3  [SOT95P237X112-3N]  (hidden comment: Comment)
IC7  value SI2318CDS-T1-GE3  [SOT95P237X112-3N]  (hidden comment: Comment)
IC8  value SI2318CDS-T1-GE3  [SOT95P237X112-3N]  (hidden comment: Comment)
J4  39-30-1039  Parameter 1: 3x1  Parameter 2: Mini  [39-30-1039]
J5  Parameter 1: 4x1  Parameter 2: Micro  [43650-0428]  (hidden comment: 43650-0428)
J6  value PJ-063BH  [CUI_PJ-063BH]  (hidden comment: Comment)
J8  43650-0527  Parameter 1: 5x1  Parameter 2: Micro  [43650-0527]
J10  43650-0328  Parameter 1: 3x1  Parameter 2: Micro  [43650-0328]
J11  43045-1228  Parameter 1: 6x2  Parameter 2: Micro  [43045-1228]
J12  43650-0228  Parameter 1: 2x1  Parameter 2: Micro  [43650-0228]
J?  Parameter 1: 8x1  Parameter 2: Micro  [43650-0829]  (hidden comment: 43650-0829)
R75  Parameter 1: 2k, 1%  [C_0603]  (hidden comment: RMCF0603FT2K00)
R76  Parameter 1: 2k, 1%  [C_0603]  (hidden comment: RMCF0603FT2K00)
R77  Parameter 1: 2k, 1%  [C_0603]  (hidden comment: RMCF0603FT2K00)
R78  Parameter 1: 2k, 1%  [C_0603]  (hidden comment: RMCF0603FT2K00)

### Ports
48V AUX OUT (in), CONTACTOR_OUT_[1..4] (in), ESTOP (harness ESTOP_CONN), JETSON PWR OUT (in), LED (harness LED), LED HIGHSIDE EF (in), NTWK_SW_OUT (in), POE_OUT_[1..6] (in), RS485 (harness RS485)

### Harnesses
ESTOP_CONN: ESTOP_SENSE, ESTOP_TRIG
LED: GREEN EN, YELLOW EN, RED EN, BLUE EN
RS485: RS_485_N, RS_485_P

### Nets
+5V: F?.2
GND: D12.1(A1) D13.1(A1) D14.1(A1) D15.1(A1) D16.1(A1) D17.1(A1) D18.1(A1) D19.1(A1) D23.2(A) D24.2(A) D25.2(A) D30.1(A1) D32.2(A) D33.1(A1) D34.1(A1) D35.1(A1) D36.1(A1) D37.1(A1) D38.1(A1) D39.1(A1) IC5.2 IC6.2 IC7.2 IC8.2 J4.3 J5.4 J6.2 J6.S1(SHIELD) J6.S2(SHIELD) J10.3 J11.2 J11.4 J11.6 J11.8 J11.10 J11.12 J12.2 J?.2 J?.4 J?.6 J?.8 R75.1 R76.1 R77.1 R78.1
BLUE_EN: D29.1 IC8.1 ; port LED.BLUE EN
BLUE_LED_LOWSIDE: IC8.3 J8.5
CONTACTOR_OUT_1: D30.2(A2) D31.1 J?.1
CONTACTOR_OUT_2: D17.2(A2) D20.1 J?.3
CONTACTOR_OUT_3: D18.2(A2) D21.1 J?.5
CONTACTOR_OUT_4: D19.2(A2) D22.1 J?.7
ESTOP_SENSE: J10.1 ; port ESTOP.ESTOP_SENSE
ESTOP_TRIG: J10.2 ; port ESTOP.ESTOP_TRIG
GREEN_EN: D26.1 IC5.1 ; port LED.GREEN EN
GREEN_LED_LOWSIDE: IC5.3 J8.2
JETSON OUT: D13.2(A2) J6.1 ; port JETSON PWR OUT
OUT3: D12.2(A2) J4.1 ; port 48V AUX OUT
OUT4: D39.2(A2) J12.1 ; port NTWK_SW_OUT
OUT4: D16.2(A2) J8.1 ; port LED HIGHSIDE EF  [a separate net that carries the same name]
POE_OUT_1: D33.2(A2) J11.1
POE_OUT_2: D34.2(A2) J11.3
POE_OUT_3: D35.2(A2) J11.5
POE_OUT_4: D36.2(A2) J11.7
POE_OUT_5: D37.2(A2) J11.9
POE_OUT_6: D38.2(A2) J11.11
RED_EN: D28.1 IC7.1 ; port LED.RED EN
RED_LED_LOWSIDE: IC7.3 J8.4
RS_485_N: D15.2(A2) J5.3 ; port RS485.RS_485_P
RS_485_P: D14.2(A2) J5.2 ; port RS485.RS_485_N
YELLOW_EN: D27.1 IC6.1 ; port LED.YELLOW EN
YELLOW_LED_LOWSIDE: IC6.3 J8.3
NetD26_2: D26.2 R75.2
NetD27_2: D27.2 R76.2
NetD28_2: D28.2 R77.2
NetD29_2: D29.2 R78.2
NetF?_1: F?.1 J5.1

Not connected (* = marked no-connect by the designer): D20 2; D21 2; D22 2; D23 1(K); D24 1(K); D25 1(K); D31 2; D32 1(K); J4 2*

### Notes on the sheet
- (near J10) ESTOP CONN

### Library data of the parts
D12-D19 D30 D33-D39 = D_TVS: Trans Voltage Suppressor Diode, 400W, 51V V(RWM), Bidirectional, 1 Element, Silicon, DO-214AC; Manufacturer: Littelfuse; Manufacturer Part Number: SMAJ51CA; Package Body Material: Plastic; Max Breakdown Voltage: 62.7V; Min Breakdown Voltage: 56.7V; Breakdown Voltage-Nom: 59.7V; Clamping Voltage-Max: 82.4V; Number of Elements: 1; Time @ Peak Reflow Temperature-Max (s): 40s; Qualification Status: Not Qualified
D20-D22 D31 = SMAZ36-13-F: Zener Diode, 36V V(Z), 5%, 1W, Silicon, Unidirectional; Manufacturer: Diodes; Package Body Material: Plastic; Dynamic Impedance-Max: 40R; Number of Elements: 1; Time @ Peak Reflow Temperature-Max (s): 40s; Test Current: 10mA; Qualification Status: Not Qualified
D23-D25 D32 = D: Rectifier Diode, Schottky, 1 Phase, 1 Element, 1A, 40V V(RRM), Silicon; Manufacturer: MCC; Manufacturer Part Number: SM5819PL-TP; Package Body Material: Plastic; Non-rep Pk Forward Current-Max: 30A; Number of Elements: 1; Max Power Dissipation: 1.14W; Time @ Peak Reflow Temperature-Max (s): 10s; Qualification Status: Not Qualified
D26 = B1931NG--20D001114U1930: Led Green Diffused 0603 SMD; Manufacturer: Inolux
D27 = B1931UY--20D000114U1930: Led Yellow Clear 1608 SMD; Manufacturer: Inolux
D28 = B1931USD-20D000814U1930: as D10 on sheet EFUSE
D29 = B1931NB--20C007614U1930: Led Blue Clear 1608 SMD; Manufacturer: Inolux
F? = 0ZCF0050FF2C: PTC Resettable Fuse, 60V, 0.3ohm, Surface Mount; Manufacturer: Bel; Power: 1.5W; Thermistor Application: TEMPERATURE SENSING
IC5-IC8 = SI2318CDS-T1-GE3: Small Signal Field-Effect Transistor, 5.6A I(D), 40V, 1-Element, N-Channel, Silicon, Metal-oxide Semiconductor FET, TO-236AB; MANUFACTURER_NAME: Vishay; Manufacturer: Vishay Siliconix; Package Body Material: Plastic; Drain-source On Resistance-Max: 42mR; Number of Elements: 1; Operating Mode: ENHANCEMENT MODE; Power Dissipation-Max (Abs): 2.1W; Time @ Peak Reflow Temperature-Max (s): 30s; Transistor Application: SWITCHING; Qualification Status: Not Qualified
J4 = 39-30-1039: Rectangular Power Connector, 3 Contact(s), Male, Solder Terminal, Plug; Manufacturer: Molex; Manufacturer Series: 5566; Connector Type: Power,Rectangular; Option: General Purpose; Board Mounting Option: COMPLIANT BOARDLOCK; Contact Resistance: 10mR; Contact Style: SQ PIN-SKT; Dielectric Withstanding Voltage (AC): 1.5kV; Durability: 30Cycles; Empty Shell: No; Insulation Resistance: 1GR; Mating Information: MULTIPLE MATING PARTS AVAILABLE; Rated Current (Signal): 9A; Number of Contacts: 3; Insertion Force-Max: 6.672N; Number Of Connectors: 1; Polarization Key: HOUSING SIDE; Withdrawl Force-Min: 3.1136N; Body Breadth: 0.213inch; Body Depth: 0.504inch; Body Length: 0.543inch; Mounting Option 1: POLARIZED LCK; Mounting Option 2: LOCKING; Plating Thickness: 35uin; Mating Contact Pitch: 0.165inch; Reference Standard: UL; Reliability: COMMERCIAL
J5 = 43650-0428: Rectangular Power Connector, 4 Contact(s), Female, Solder Terminal; Manufacturer: Molex; Manufacturer Series: 43650; Connector Type: Power,Rectangular; Option: General Purpose; Board Mounting Option: PEG; Body/Shell Style: RECEPTACLE; Contact Resistance: 10mR; Contact Style: SQ PIN-SKT; Dielectric Withstanding Voltage (AC): 1.5kV; Durability: 30Cycles; Empty Shell: No; Insertion Force-Max: 8.0064N; Insulation Resistance: 1GR; Mating Information: MULTIPLE MATING PARTS AVAILABLE; Number Of Connectors: 1; Polarization Key: POLARIZED HOUSING; Rated Current (Signal): 5A; Number of Contacts: 4; Withdrawl Force-Min: 3.614N; Body Breadth: 0.219inch; Body Depth: 0.39inch; Body Length: 0.616inch; Mating Contact Pitch: 0.118inch; Mounting Option 1: POLARIZED LCK; Mounting Option 2: LOCKING; Plating Thickness: 15uin; Reference Standard: UL; Reliability: COMMERCIAL
J6 = PJ-063BH: Circular DC Power Connector, 24V, 8A, 2.5mm Dia; MANUFACTURER: CUI INC
J8 = 43650-0527: Rectangular Power Connector, 5 Contact(s), Female, Solder Terminal; Manufacturer: Molex; Connector Type: Power,Rectangular; Option: General Purpose; Board Mounting Option: PEG; Body/Shell Style: RECEPTACLE; Contact Resistance: 10mR; Contact Style: SQ PIN-SKT; Dielectric Withstanding Voltage (AC): 1.5kV; Durability: 30Cycles; Empty Shell: No; Insertion Force-Max: 8.0064N; Insulation Resistance: 1GR; Mating Information: MULTIPLE MATING PARTS AVAILABLE; Number Of Connectors: 1; Polarization Key: POLARIZED HOUSING; Rated Current (Signal): 5A; Number of Contacts: 5; Withdrawl Force-Min: 3.614N; Body Breadth: 0.219inch; Body Depth: 0.39inch; Body Length: 0.734inch; Mating Contact Pitch: 0.118inch; Mounting Option 1: POLARIZED LCK; Mounting Option 2: LOCKING; Plating Thickness: 100uin; Reference Standard: UL; Reliability: COMMERCIAL
J10 = 43650-0328: Rectangular Power Connector, 3 Contact(s), Female, Solder Terminal; Manufacturer: Molex; Manufacturer Series: 43650; Connector Type: Power,Rectangular; Option: General Purpose; Board Mounting Option: PEG; Body/Shell Style: RECEPTACLE; Contact Resistance: 10mR; Contact Style: SQ PIN-SKT; Dielectric Withstanding Voltage (AC): 1.5kV; Durability: 30Cycles; Empty Shell: No; Insertion Force-Max: 8.0064N; Insulation Resistance: 1GR; Mating Information: MULTIPLE MATING PARTS AVAILABLE; Number Of Connectors: 1; Polarization Key: POLARIZED HOUSING; Rated Current (Signal): 5A; Number of Contacts: 3; Withdrawl Force-Min: 3.614N; Body Breadth: 0.219inch; Body Depth: 0.39inch; Body Length: 0.498inch; Mating Contact Pitch: 0.118inch; Mounting Option 1: POLARIZED LCK; Mounting Option 2: LOCKING; Plating Thickness: 15uin; Reference Standard: UL; Reliability: COMMERCIAL
J11 = 43045-1228: Board Connector, 12 Contact(s), 2 Row(s), Male, Straight, Solder Terminal, Locking, Black Insulator, Receptacle; Manufacturer: Molex; Throw Configuration: S0P12; Option: General Purpose; Board Mounting Option: PEG; Contact Resistance: 10mR; Contact Style: SQ PIN-SKT; Filter Feature: No; Insertion Force-Max: 8.0064N; Insulation Resistance: 1GR; Mating Information: MULTIPLE MATING PARTS AVAILABLE; Number Of Connectors: 1; Number of Rows Loaded: 2; Rated Current (Signal): 2.5A; Number of Contacts: 12; Withdrawl Force-Min: 3.5584N; Body Breadth: 0.29inch; Body Depth: 0.39inch; Body Length: 0.852inch; Plating Thickness: 15uin; Reference Standard: UL; Reliability: COMMERCIAL
J12 = 43650-0228: Rectangular Power Connector, 2 Contact(s), Female, Solder Terminal; Manufacturer: Molex; Manufacturer Series: 43650; Connector Type: Power,Rectangular; Option: General Purpose; Board Mounting Option: PEG; Body/Shell Style: RECEPTACLE; Contact Resistance: 10mR; Contact Style: SQ PIN-SKT; Dielectric Withstanding Voltage (AC): 1.5kV; Durability: 30Cycles; Empty Shell: No; Insertion Force-Max: 8.0064N; Insulation Resistance: 1GR; Mating Information: MULTIPLE MATING PARTS AVAILABLE; Number Of Connectors: 1; Polarization Key: POLARIZED HOUSING; Rated Current (Signal): 5A; Number of Contacts: 2; Withdrawl Force-Min: 3.614N; Body Breadth: 0.219inch; Body Depth: 0.39inch; Body Length: 0.38inch; Mating Contact Pitch: 0.118inch; Mounting Option 1: POLARIZED LCK; Mounting Option 2: LOCKING; Plating Thickness: 15uin; Reference Standard: UL; Reliability: COMMERCIAL
J? = 43650-0829: Rectangular Power Connector, 8 Contact(s), Female, Solder Terminal; Manufacturer: Molex; Manufacturer Series: 43650; Connector Type: Power,Rectangular; Option: General Purpose; Board Mounting Option: PEG; Body/Shell Style: RECEPTACLE; Contact Resistance: 10mR; Contact Style: SQ PIN-SKT; Dielectric Withstanding Voltage (AC): 1.5kV; Durability: 30Cycles; Empty Shell: No; Insertion Force-Max: 8.0064N; Insulation Resistance: 1GR; Mating Information: MULTIPLE MATING PARTS AVAILABLE; Number Of Connectors: 1; Polarization Key: POLARIZED HOUSING; Rated Current (Signal): 5A; Number of Contacts: 8; Withdrawl Force-Min: 3.614N; Body Breadth: 0.219inch; Body Depth: 0.39inch; Body Length: 1.089inch; Mating Contact Pitch: 0.118inch; Mounting Option 1: POLARIZED LCK; Mounting Option 2: LOCKING; Plating Thickness: 30uin; Reference Standard: UL; Reliability: COMMERCIAL
R75-R78 = RMCF0603FT2K00: as R72 on sheet EFUSE

## Sheet I2C EXPANDER.SchDoc
size 508 x 203 mm
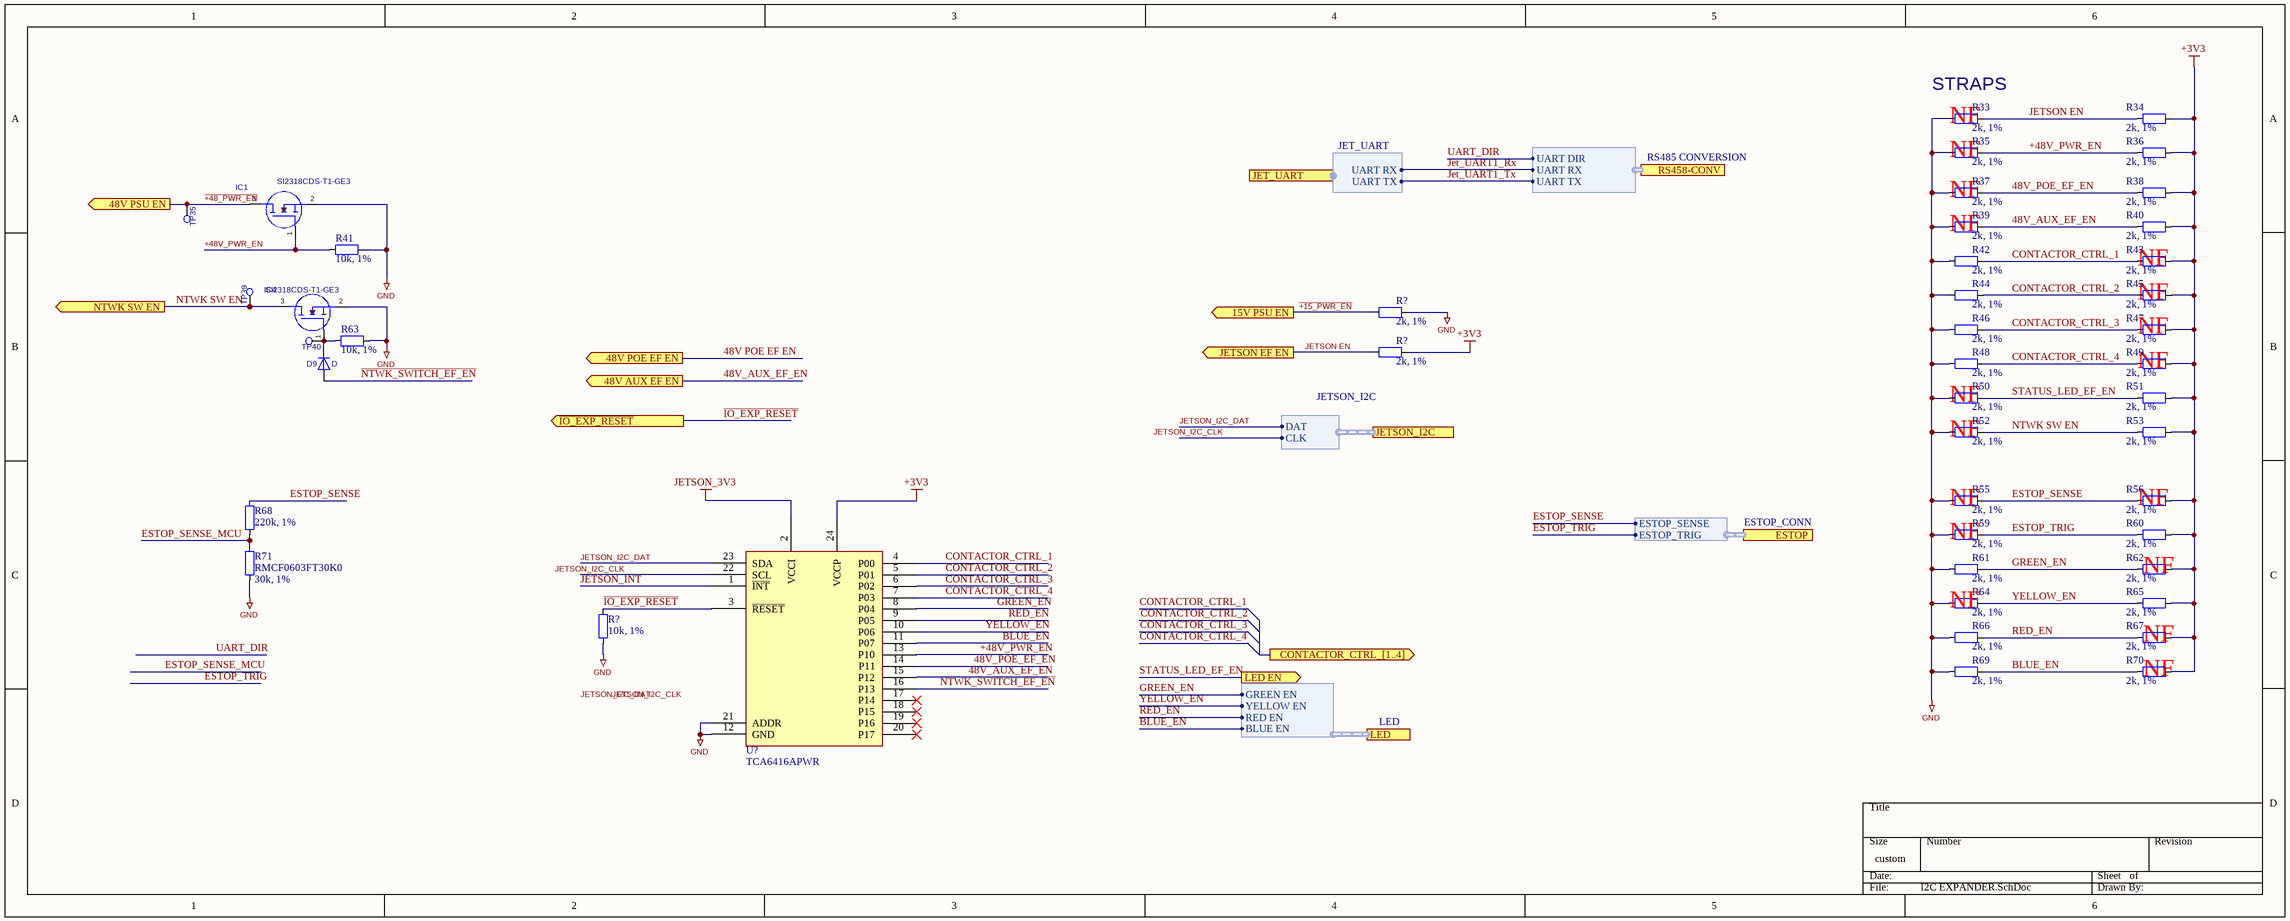
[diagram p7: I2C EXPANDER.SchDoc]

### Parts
(Parts that share a designator on the sheet are numbered #1, #2 ... from top to bottom, then left to right.)
D9  value D  [D_SOD-123F]  (hidden comment: Comment)
IC1  SI2318CDS-T1-GE3  [SOT95P237X112-3N]
IC4  SI2318CDS-T1-GE3  [SOT95P237X112-3N]
R33  Parameter 1: 2k, 1%  [C_0603]  (hidden comment: RMCF0603FT2K00)
R34  Parameter 1: 2k, 1%  [C_0603]  (hidden comment: RMCF0603FT2K00)
R35  Parameter 1: 2k, 1%  [C_0603]  (hidden comment: RMCF0603FT2K00)
R36  Parameter 1: 2k, 1%  [C_0603]  (hidden comment: RMCF0603FT2K00)
R37  Parameter 1: 2k, 1%  [C_0603]  (hidden comment: RMCF0603FT2K00)
R38  Parameter 1: 2k, 1%  [C_0603]  (hidden comment: RMCF0603FT2K00)
R39  Parameter 1: 2k, 1%  [C_0603]  (hidden comment: RMCF0603FT2K00)
R40  Parameter 1: 2k, 1%  [C_0603]  (hidden comment: RMCF0603FT2K00)
R41  Parameter 1: 10k, 1%  [R_0603]  (hidden comment: RMCF0603FT10K0)
R42  Parameter 1: 2k, 1%  [C_0603]  (hidden comment: RMCF0603FT2K00)
R43  Parameter 1: 2k, 1%  [C_0603]  (hidden comment: RMCF0603FT2K00)
R44  Parameter 1: 2k, 1%  [C_0603]  (hidden comment: RMCF0603FT2K00)
R45  Parameter 1: 2k, 1%  [C_0603]  (hidden comment: RMCF0603FT2K00)
R46  Parameter 1: 2k, 1%  [C_0603]  (hidden comment: RMCF0603FT2K00)
R47  Parameter 1: 2k, 1%  [C_0603]  (hidden comment: RMCF0603FT2K00)
R48  Parameter 1: 2k, 1%  [C_0603]  (hidden comment: RMCF0603FT2K00)
R49  Parameter 1: 2k, 1%  [C_0603]  (hidden comment: RMCF0603FT2K00)
R50  Parameter 1: 2k, 1%  [C_0603]  (hidden comment: RMCF0603FT2K00)
R51  Parameter 1: 2k, 1%  [C_0603]  (hidden comment: RMCF0603FT2K00)
R52  Parameter 1: 2k, 1%  [C_0603]  (hidden comment: RMCF0603FT2K00)
R53  Parameter 1: 2k, 1%  [C_0603]  (hidden comment: RMCF0603FT2K00)
R55  Parameter 1: 2k, 1%  [C_0603]  (hidden comment: RMCF0603FT2K00)
R56  Parameter 1: 2k, 1%  [C_0603]  (hidden comment: RMCF0603FT2K00)
R59  Parameter 1: 2k, 1%  [C_0603]  (hidden comment: RMCF0603FT2K00)
R60  Parameter 1: 2k, 1%  [C_0603]  (hidden comment: RMCF0603FT2K00)
R61  Parameter 1: 2k, 1%  [C_0603]  (hidden comment: RMCF0603FT2K00)
R62  Parameter 1: 2k, 1%  [C_0603]  (hidden comment: RMCF0603FT2K00)
R63  Parameter 1: 10k, 1%  [R_0603]  (hidden comment: RMCF0603FT10K0)
R64  Parameter 1: 2k, 1%  [C_0603]  (hidden comment: RMCF0603FT2K00)
R65  Parameter 1: 2k, 1%  [C_0603]  (hidden comment: RMCF0603FT2K00)
R66  Parameter 1: 2k, 1%  [C_0603]  (hidden comment: RMCF0603FT2K00)
R67  Parameter 1: 2k, 1%  [C_0603]  (hidden comment: RMCF0603FT2K00)
R68  Parameter 1: 220k, 1%  [R_0603]  (hidden comment: RMCF0603FT220K)
R69  Parameter 1: 2k, 1%  [C_0603]  (hidden comment: RMCF0603FT2K00)
R70  Parameter 1: 2k, 1%  [C_0603]  (hidden comment: RMCF0603FT2K00)
R71  RMCF0603FT30K0  Parameter 1: 30k, 1%  [R_0603]
R?#1  Parameter 1: 2k, 1%  [C_0603]  (hidden comment: RMCF0603FT2K00)
R?#2  Parameter 1: 2k, 1%  [C_0603]  (hidden comment: RMCF0603FT2K00)
R?#3  Parameter 1: 10k, 1%  [R_0603]  (hidden comment: RMCF0603FT10K0)
TP35  Comment  [TestPoint_Pad_D1.0mm]  (value not drawn)
TP39  Comment  [TestPoint_Pad_D1.0mm]  (value not drawn)
TP40  Comment  [TestPoint_Pad_D1.0mm]  (value not drawn)
U?  TCA6416APWR  [TSSOP24]

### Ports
15V PSU EN (out), 48V AUX EF EN (out), 48V POE EF EN (out), 48V PSU EN (out), CONTACTOR_CTRL_[1..4] (out), ESTOP (harness ESTOP_CONN), JET_UART (harness JET_UART), JETSON EF EN (out), JETSON_I2C (harness JETSON_I2C), LED (harness LED), LED EN (out), NTWK SW EN (out), RS458-CONV (harness RS485 CONVERSION), ~{IO_EXP_RESET} (out)

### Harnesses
ESTOP_CONN: ESTOP_SENSE, ESTOP_TRIG
LED: GREEN EN, YELLOW EN, RED EN, BLUE EN
RS485 CONVERSION: UART RX, UART TX, UART DIR
JET_UART: UART RX, UART TX
JETSON_I2C: DAT, CLK

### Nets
+3V3: R34.2 R36.2 R38.2 R40.2 R43.2 R45.2 R47.2 R49.2 R51.2 R53.2 R56.2 R60.2 R62.2 R65.2 R67.2 R70.2 R?#2.1 U?.24(VCCP)
GND: IC1.2 IC4.2 R33.2 R35.2 R37.2 R39.2 R41.2 R42.2 R44.2 R46.2 R48.2 R50.2 R52.2 R55.2 R59.2 R61.2 R63.2 R64.2 R66.2 R69.2 R71.2 R?#1.1 R?#3.2 U?.12(GND) U?.21(ADDR)
JETSON_3V3: U?.2(VCCI)
48V_AUX_EF_EN: R39.1 R40.1 U?.15(P12) ; port 48V AUX EF EN
48V_POE_EF_EN: R37.1 R38.1 U?.14(P11)
+48V_PWR_EN: IC1.1 R35.1 R36.1 R41.1 U?.13(P10)
~{+15_PWR_EN}: R?#1.2 ; port 15V PSU EN
~{+48_PWR_EN}: IC1.3 TP35.1 ; port 48V PSU EN
~{IO_EXP_RESET}: R?#3.1 U?.3(~{RESET}) ; port ~{IO_EXP_RESET}
~{JETSON}_~{INT}: U?.1(~{INT})
~{NTWK_SWITCH_EF_EN}: D9.2(A) U?.16(P13)
BLUE_EN: R69.1 R70.1 U?.11(P07) ; port LED.BLUE EN
CONTACTOR_CTRL_1: R42.1 R43.1 U?.4(P00)
CONTACTOR_CTRL_2: R44.1 R45.1 U?.5(P01)
CONTACTOR_CTRL_3: R46.1 R47.1 U?.6(P02)
CONTACTOR_CTRL_4: R48.1 R49.1 U?.7(P03)
ESTOP_SENSE: R55.1 R56.1 R68.1 ; port ESTOP.ESTOP_SENSE
ESTOP_SENSE_MCU: R68.2 R71.1
ESTOP_TRIG: R59.1 R60.1 ; port ESTOP.ESTOP_TRIG
GREEN_EN: R61.1 R62.1 U?.8(P04) ; port LED.GREEN EN
Jet_UART1_Rx: port RS458-CONV.UART RX, port JET_UART.UART RX
Jet_UART1_Tx: port RS458-CONV.UART TX, port JET_UART.UART TX  [project net Jet_UART1_Rx_IN]
JETSON EN: R33.1 R34.1 R?#2.2 ; port JETSON EF EN  [project net EN1]
JETSON_I2C_CLK: U?.22(SCL) ; port JETSON_I2C.CLK
JETSON_I2C_DAT: U?.23(SDA) ; port JETSON_I2C.DAT
NTWK SW EN: IC4.3 R52.1 R53.1 TP39.1 ; port NTWK SW EN  [project net EN4]
RED_EN: R66.1 R67.1 U?.9(P05) ; port LED.RED EN
STATUS_LED_EF_EN: R50.1 R51.1 ; port LED EN  [project net EN4]
YELLOW_EN: R64.1 R65.1 U?.10(P06) ; port LED.YELLOW EN
NetD9_1: D9.1(K) IC4.1 R63.1 TP40.1

Not connected (* = marked no-connect by the designer): U? 17(P14)* 18(P15)* 19(P16)* 20(P17)*

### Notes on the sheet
- (near R33) STRAPS
- (near R33) NF
- (near R35) NF
- (near R39) NF
- (near R37) NF
- (near R45) NF
- (near R43) NF
- (near R49) NF
- (near R47) NF
- (near R50) NF
- (near R52) NF
- (near R55) NF
- (near R56) NF
- (near R59) NF
- (near R62) NF
- (near R64) NF
- (near R67) NF
- (near R70) NF
- Labels drawn without touching a wire or pin: JETSON_I2C_CLK, JETSON_I2C_DAT

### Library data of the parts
D9 = D: as D23 on sheet OUTPUT CONNECTORS
IC1 IC4 = SI2318CDS-T1-GE3: as IC5 on sheet OUTPUT CONNECTORS
R33-R40 R42-R53 R55 R56 R59-R62 R64-R67 R69 R70 R?#1 R?#2 = RMCF0603FT2K00: as R72 on sheet EFUSE
R41 R63 R?#3 = RMCF0603FT10K0: Fixed Resistor, Metal Glaze/thick Film, 0.1W, 10000ohm, 75V, 1% +/-Tol, 100ppm/Cel, Surface Mount, 0603; Manufacturer: Stackpole Electronics; Power: 100mW; Rated Temperature: 70°C; Temperature Coefficient (ppm/Cel): 100; Package Height: 0.45mm; Package Length: 1.55mm; Package Width: 0.8mm; Reference Standard: AEC-Q200; Value: 10k
R68 = RMCF0603FT220K: Fixed Resistor, Metal Glaze/thick Film, 0.1W, 220000ohm, 75V, 1% +/-Tol, 100ppm/Cel, Surface Mount, 0603; Manufacturer: Stackpole Electronics; Power: 100mW; Rated Temperature: 70°C; Temperature Coefficient (ppm/Cel): 100; Package Height: 0.45mm; Package Length: 1.55mm; Package Width: 0.8mm; Reference Standard: AEC-Q200; Value: 220k
R71 = RMCF0603FT30K0: as R73 on sheet EFUSE
TP35 TP39 TP40 = TestPoint_1: Value: KeySwitch IN
U? = TCA6416APWR: Parallel I/O Port, 16-Bit, 16 I/O, CMOS, PDSO24; Manufacturer: Texas Instruments; Package Body Material: Plastic; Power Supplies: 1.8/5V; Max Supply Voltage: 5.5V; Min Supply Voltage: 1.65V; Nominal Supply Voltage: 1.8V; Number of Bits: 16; Number of Ports: 2; Package Equivalence Code: TSSOP24,.25; Qualification Status: Not Qualified

## Sheet TEMPERATURE SENSORS.SchDoc
size A
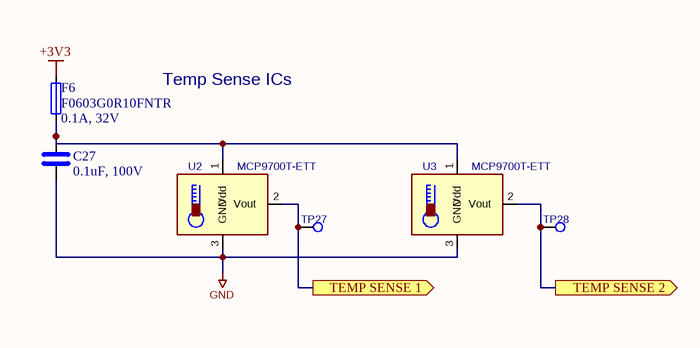
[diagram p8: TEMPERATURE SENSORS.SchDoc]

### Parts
C27  Parameter 1: 0.1uF, 100V  [C_0603]  (hidden comment: CL10B104KC8NNNC)
F6  F0603G0R10FNTR  Parameter 1: 0.1A, 32V  [FUSE_0603]
TP27  Comment  [TestPoint_Pad_D1.0mm]  (value not drawn)
TP28  Comment  [TestPoint_Pad_D1.0mm]  (value not drawn)
U2  value MCP9700T-ETT  [SOT-23]  (hidden comment: Comment)
U3  value MCP9700T-ETT  [SOT-23]  (hidden comment: Comment)

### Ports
TEMP SENSE 1 (out), TEMP SENSE 2 (out)

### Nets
+3V3: F6.1
GND: C27.2 U2.3(GND) U3.3(GND)
TEMP SENSE 1: TP27.1 U2.2(Vout) ; port TEMP SENSE 1
TEMP SENSE 2: TP28.1 U3.2(Vout) ; port TEMP SENSE 2
NetC27_1: C27.1 F6.2 U2.1(Vdd) U3.1(Vdd)

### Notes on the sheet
- Temp Sense ICs

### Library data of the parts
C27 = CL10B104KC8NNNC: as C33 on sheet 3V3 PSU
F6 = F0603G0R10FNTR: as F7 on sheet ADC ARRAY
TP27 TP28 = TestPoint_1: Value: KeySwitch IN
U2 U3 = MCP9700T-ETT

## Sheet UART TO RS485.SchDoc
size A
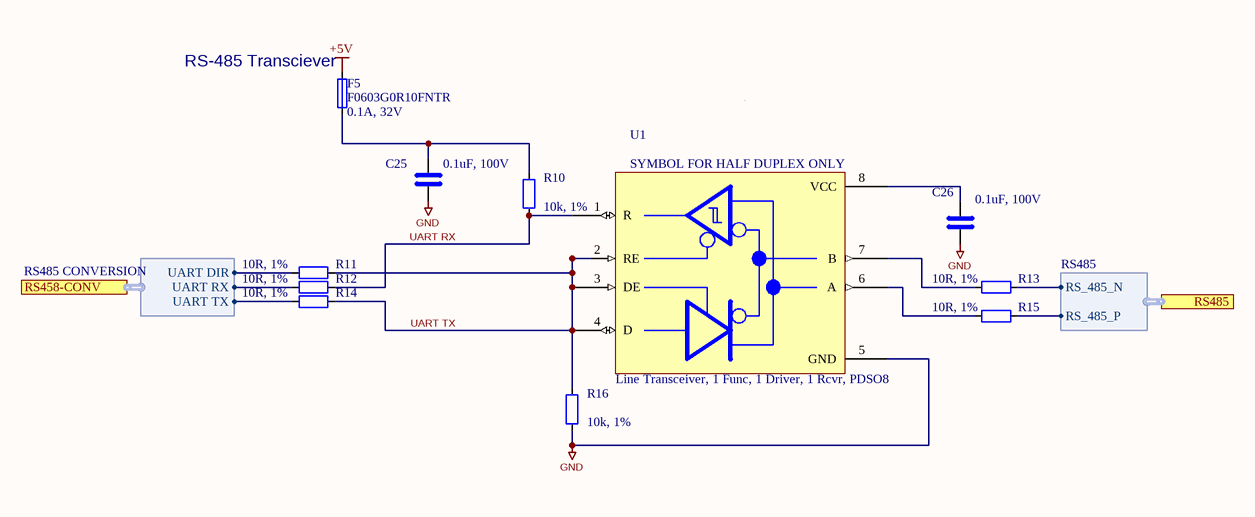
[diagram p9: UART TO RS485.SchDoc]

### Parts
C25  Parameter 1: 0.1uF, 100V  [C_0603]  (hidden comment: CL10B104KC8NNNC)
C26  Parameter 1: 0.1uF, 100V  [C_0603]  (hidden comment: CL10B104KC8NNNC)
F5  F0603G0R10FNTR  Parameter 1: 0.1A, 32V  [FUSE_0603]
R10  Parameter 1: 10k, 1%  [R_0603]  (hidden comment: RMCF0603FT10K0)
R11  Parameter 1: 10R, 1%  [R_0603]  (hidden comment: RMCF0603FT10R0)
R12  Parameter 1: 10R, 1%  [R_0603]  (hidden comment: RMCF0603FT10R0)
R13  Parameter 1: 10R, 1%  [R_0603]  (hidden comment: RMCF0603FT10R0)
R14  Parameter 1: 10R, 1%  [R_0603]  (hidden comment: RMCF0603FT10R0)
R15  Parameter 1: 10R, 1%  [R_0603]  (hidden comment: RMCF0603FT10R0)
R16  Parameter 1: 10k, 1%  [R_0603]  (hidden comment: RMCF0603FT10K0)
U1  Line Transceiver, 1 Func, 1 Driver, 1 Rcvr, PDSO8  [8-SOIC]

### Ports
RS458-CONV (harness RS485 CONVERSION), RS485 (harness RS485)

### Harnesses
RS485: RS_485_N, RS_485_P
RS485 CONVERSION: UART RX, UART TX, UART DIR

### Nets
+5V: F5.1
GND: C25.2 C26.2 R16.2 U1.5(GND)
Jet_UART1_Rx: R12.2 ; port RS458-CONV.UART RX
Jet_UART1_Rx_IN: R14.2 ; port RS458-CONV.UART TX
RS_485_N: R15.2 ; port RS485.RS_485_P
RS_485_P: R13.2 ; port RS485.RS_485_N
UART RX: R10.2 R12.1 U1.1(R)
UART TX: R11.1 R14.1 R16.1 U1.2(RE) U1.3(DE) U1.4(D)
UART_DIR: R11.2 ; port RS458-CONV.UART DIR
NetC25_1: C25.1 F5.2 R10.1
NetC26_1: C26.1 U1.8(VCC)
NetR13_1: R13.1 U1.7(B)
NetR15_1: R15.1 U1.6(A)

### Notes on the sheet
- (near F5) RS-485 Transciever

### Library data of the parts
C25 C26 = CL10B104KC8NNNC: as C33 on sheet 3V3 PSU
F5 = F0603G0R10FNTR: as F7 on sheet ADC ARRAY
R10 R16 = RMCF0603FT10K0: as R41 on sheet I2C EXPANDER
R11-R15 = RMCF0603FT10R0: Fixed Resistor, Metal Glaze/thick Film, 0.1W, 10ohm, 75V, 1% +/-Tol, 100ppm/Cel, Surface Mount, 0603; Manufacturer: Stackpole Electronics; Power: 100mW; Rated Temperature: 70°C; Value: 10R; Temperature Coefficient (ppm/Cel): 100; Package Height: 0.45mm; Package Length: 1.55mm; Package Width: 0.8mm; Reference Standard: AEC-Q200
U1 = THVD1450DR: Manufacturer: Texas Instruments; Package Body Material: Plastic; Differential Output: Yes; Driver Number of Bits: 1; Input Characteristics: DIFFERENTIAL SCHMITT TRIGGER; Receive Delay-Max: 40ns; Max Supply Voltage: 5.5V; Min Supply Voltage: 3V; Nominal Supply Voltage: 5V; Transmit Delay-Max: 20ns

## Sheet 48V AND 15V PSU.SchDoc
size 381 x 241 mm
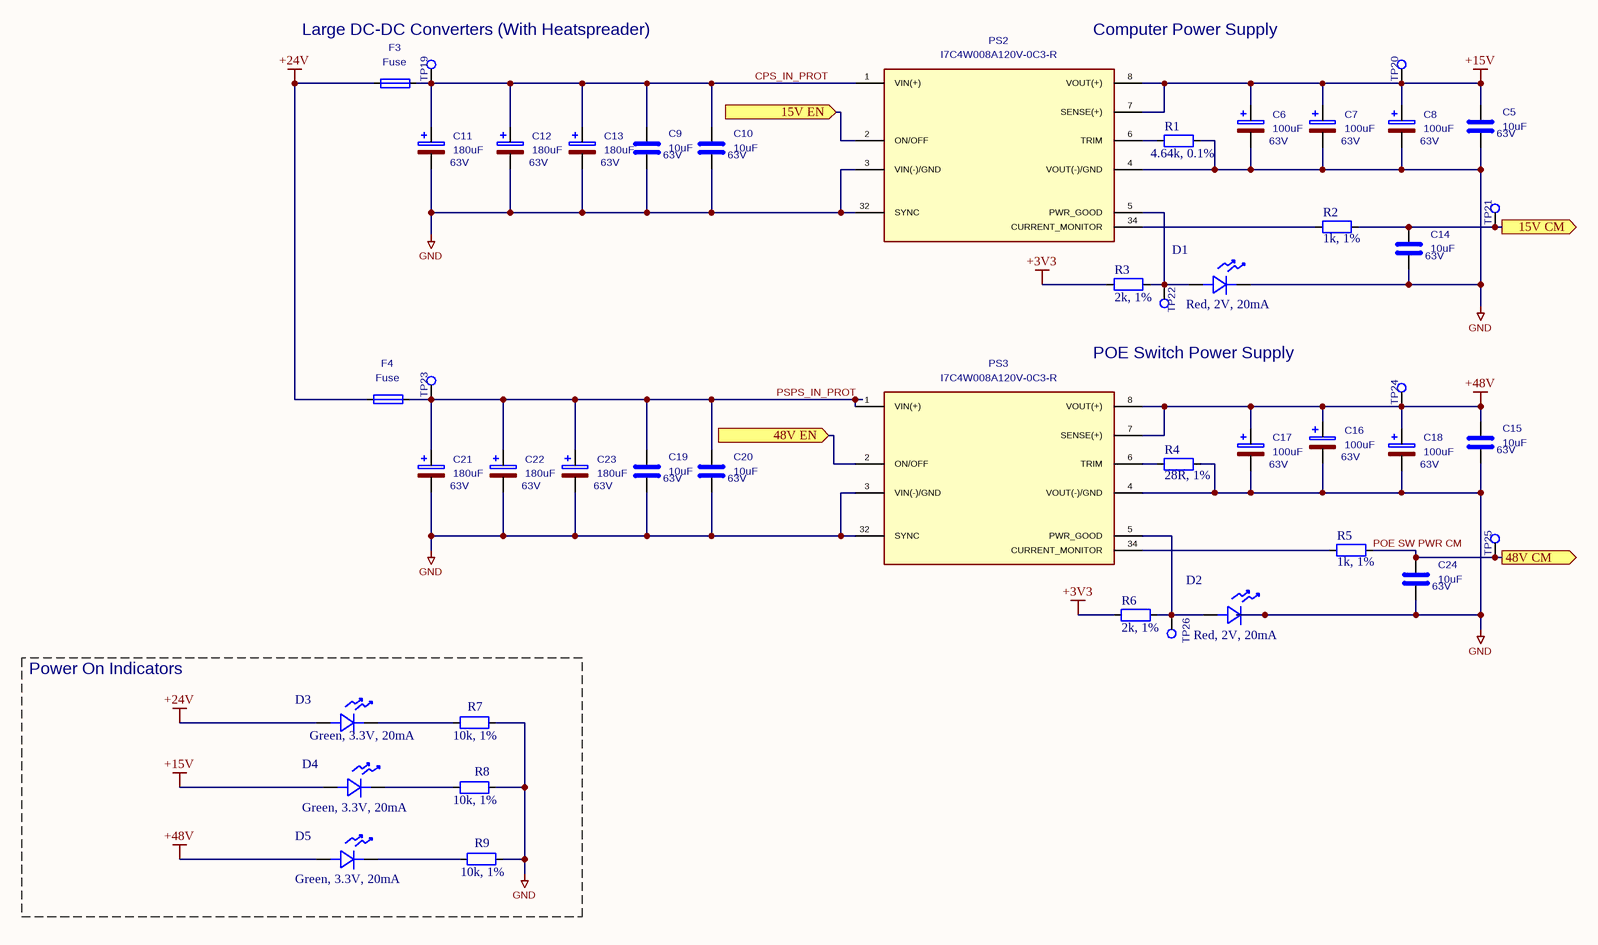
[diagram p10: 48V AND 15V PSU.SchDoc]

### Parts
C5  value 10uF  Voltage: 63V  [C_1210_3225Metric]  (hidden comment: Comment)
C6  value 100uF  Voltage: 63V  [CP_Elec_10x12.6]  (hidden comment: Comment)
C7  value 100uF  Voltage: 63V  [CP_Elec_10x12.6]  (hidden comment: Comment)
C8  value 100uF  Voltage: 63V  [CP_Elec_10x12.6]  (hidden comment: Comment)
C9  value 10uF  Voltage: 63V  [C_1210_3225Metric]  (hidden comment: Comment)
C10  value 10uF  Voltage: 63V  [C_1210_3225Metric]  (hidden comment: Comment)
C11  value 180uF  Voltage: 63V  [CP_Elec_10x12.6]  (hidden comment: Comment)
C12  value 180uF  Voltage: 63V  [CP_Elec_10x12.6]  (hidden comment: Comment)
C13  value 180uF  Voltage: 63V  [CP_Elec_10x12.6]  (hidden comment: Comment)
C14  value 10uF  Voltage: 63V  [C_1210_3225Metric]  (hidden comment: Comment)
C15  value 10uF  Voltage: 63V  [C_1210_3225Metric]  (hidden comment: Comment)
C16  value 100uF  Voltage: 63V  [CP_Elec_10x12.6]  (hidden comment: Comment)
C17  value 100uF  Voltage: 63V  [CP_Elec_10x12.6]  (hidden comment: Comment)
C18  value 100uF  Voltage: 63V  [CP_Elec_10x12.6]  (hidden comment: Comment)
C19  value 10uF  Voltage: 63V  [C_1210_3225Metric]  (hidden comment: Comment)
C20  value 10uF  Voltage: 63V  [C_1210_3225Metric]  (hidden comment: Comment)
C21  value 180uF  Voltage: 63V  [CP_Elec_10x12.6]  (hidden comment: Comment)
C22  value 180uF  Voltage: 63V  [CP_Elec_10x12.6]  (hidden comment: Comment)
C23  value 180uF  Voltage: 63V  [CP_Elec_10x12.6]  (hidden comment: Comment)
C24  value 10uF  Voltage: 63V  [C_1210_3225Metric]  (hidden comment: Comment)
D1  Parameter 1: Red, 2V, 20mA  [LED_0603]  (hidden comment: B1931USD-20D000814U1930)
D2  Parameter 1: Red, 2V, 20mA  [LED_0603]  (hidden comment: B1931USD-20D000814U1930)
D3  Parameter 1: Green, 3.3V, 20mA  [LED_0603]  (hidden comment: B1931NG--20D001114U1930)
D4  Parameter 1: Green, 3.3V, 20mA  [LED_0603]  (hidden comment: B1931NG--20D001114U1930)
D5  Parameter 1: Green, 3.3V, 20mA  [LED_0603]  (hidden comment: B1931NG--20D001114U1930)
F3  value Fuse  [FUSC9830X318N]  (hidden comment: Comment)
F4  value Fuse  [FUSC9830X318N]  (hidden comment: Comment)
PS2  value I7C4W008A120V-0C3-R  [CONV_I7C4W008A120V-0C3-R]  (hidden comment: Comment)
PS3  value I7C4W008A120V-0C3-R  [CONV_I7C4W008A120V-0C3-R]  (hidden comment: Comment)
R1  Parameter 1: 4.64k, 0.1%  [R_0603]  (hidden comment: RNCF0603BTE4K64)
R2  Parameter 1: 1k, 1%  [R_0603]  (hidden comment: RMCF0603FG1K00)
R3  Parameter 1: 2k, 1%  [C_0603]  (hidden comment: RMCF0603FT2K00)
R4  Parameter 1: 28R, 1%  [R_0603]  (hidden comment: RMCF0603FT28R0)
R5  Parameter 1: 1k, 1%  [R_0603]  (hidden comment: RMCF0603FG1K00)
R6  Parameter 1: 2k, 1%  [C_0603]  (hidden comment: RMCF0603FT2K00)
R7  Parameter 1: 10k, 1%  [R_0603]  (hidden comment: RMCF0603FT10K0)
R8  Parameter 1: 10k, 1%  [R_0603]  (hidden comment: RMCF0603FT10K0)
R9  Parameter 1: 10k, 1%  [R_0603]  (hidden comment: RMCF0603FT10K0)
TP19  Comment  [TestPoint_Pad_D1.0mm]  (value not drawn)
TP20  Comment  [TestPoint_Pad_D1.0mm]  (value not drawn)
TP21  Comment  [TestPoint_Pad_D1.0mm]  (value not drawn)
TP22  Comment  [TestPoint_Pad_D1.0mm]  (value not drawn)
TP23  Comment  [TestPoint_Pad_D1.0mm]  (value not drawn)
TP24  Comment  [TestPoint_Pad_D1.0mm]  (value not drawn)
TP25  Comment  [TestPoint_Pad_D1.0mm]  (value not drawn)
TP26  Comment  [TestPoint_Pad_D1.0mm]  (value not drawn)

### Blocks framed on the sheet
Power On Indicators: D3-D5 R7-R9

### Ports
15V CM (out), 15V EN (in), 48V CM (out), 48V EN (in)

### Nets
+3V3: R3.1 R6.1
+15V: C5.1 C6.1 C7.1 C8.1 D4.1 PS2.7(SENSE(+)) PS2.8(VOUT(+)) TP20.1
+24V: D3.1 F3.1 F4.1
+48V: C15.1 C16.1 C17.1 C18.1 D5.1 PS3.7(SENSE(+)) PS3.8(VOUT(+)) TP24.1
GND: C5.2 C6.2 C7.2 C8.2 C9.2 C10.2 C11.2 C12.2 C13.2 C14.2 C15.2 C16.2 C17.2 C18.2 C19.2 C20.2 C21.2 C22.2 C23.2 C24.2 D1.2 D2.2 PS2.3(VIN(-)/GND) PS2.4(VOUT(-)/GND) PS2.32(SYNC) PS3.3(VIN(-)/GND) PS3.4(VOUT(-)/GND) PS3.32(SYNC) R1.2 R4.2 R7.2 R8.2 R9.2
15V CM: C14.1 R2.2 TP21.1 ; port 15V CM
~{+15_PWR_EN}: PS2.2(ON/OFF) ; port 15V EN
~{+48_PWR_EN}: PS3.2(ON/OFF) ; port 48V EN
CPS_IN_PROT: C9.1 C10.1 C11.1 C12.1 C13.1 F3.2 PS2.1(VIN(+)) TP19.1
POE SW PWR CM: C24.1 R5.2 TP25.1 ; port 48V CM
PSPS_IN_PROT: C19.1 C20.1 C21.1 C22.1 C23.1 F4.2 PS3.1(VIN(+)) TP23.1
NetD1_1: D1.1 PS2.5(PWR_GOOD) R3.2 TP22.1
NetD2_1: D2.1 PS3.5(PWR_GOOD) R6.2 TP26.1
NetD3_2: D3.2 R7.1
NetD4_2: D4.2 R8.1
NetD5_2: D5.2 R9.1
NetPS2_6: PS2.6(TRIM) R1.1
NetPS2_34: PS2.34(CURRENT_MONITOR) R2.1
NetPS3_6: PS3.6(TRIM) R4.1
NetPS3_34: PS3.34(CURRENT_MONITOR) R5.1

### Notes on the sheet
- Large DC-DC Converters (With Heatspreader)
- (near PS2) Computer Power Supply
- POE Switch Power Supply

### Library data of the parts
C5 C9 C10 C14 C15 C19 C20 C24 = C: as C1 on sheet 5V0 PSU
C6-C8 C11-C13 C16-C18 C21-C23 = C_Polarized
D1 D2 = B1931USD-20D000814U1930: as D10 on sheet EFUSE
D3-D5 = B1931NG--20D001114U1930: as D26 on sheet OUTPUT CONNECTORS
F3 F4 = Fuse: Fuse Chip Medium Time Delay Acting 25A 250V SMD Solder Pad 3912 9.8 X 3.05 X 4.06mm Ceramic; Manufacturer: Bel; Manufacturer Part Number: 0678L9250-02; Fuse Type: Board Mount (Cartridge Style Excluded); Voltage Rating (DC): 72V; DC Cold Resistance: 1.9mR
PS2 PS3 = I7C4W008A120V-0C3-R: MANUFACTURER: TDK; SNAPEDA_PN: i7C4W012A050V-0C3-R
R1 = RNCF0603BTE4K64: Fixed Resistor, Thin Film, 0.166W, 4640ohm, 100V, 0.1% +/-Tol, 25ppm/Cel, Surface Mount, 0603; Manufacturer: Stackpole Electronics; Additional Feature: PRECISION; Power: 166mW; Rated Temperature: 70°C; Temperature Coefficient (ppm/Cel): 25; Package Height: 0.45mm; Package Length: 1.55mm; Package Width: 0.8mm; Reference Standard: AEC-Q200; Value: 4.64k
R2 R5 = RMCF0603FG1K00: Fixed Resistor, Metal Glaze/thick Film, 0.1W, 1000ohm, 75V, 1% +/-Tol, 100ppm/Cel, Surface Mount, 0603; Manufacturer: Stackpole Electronics; Power: 100mW; Rated Temperature: 70°C; Temperature Coefficient (ppm/Cel): 100; Package Height: 0.45mm; Package Length: 1.55mm; Package Width: 0.8mm; Reference Standard: AEC-Q200; Value: 1k
R3 R6 = RMCF0603FT2K00: as R72 on sheet EFUSE
R4 = RMCF0603FT28R0: Fixed Resistor, Metal Glaze/thick Film, 0.1W, 28ohm, 75V, 1% +/-Tol, 100ppm/Cel, Surface Mount, 0603; Manufacturer: Stackpole Electronics; Power: 100mW; Rated Temperature: 70°C; Temperature Coefficient (ppm/Cel): 100; Package Height: 0.45mm; Package Length: 1.55mm; Package Width: 0.8mm; Reference Standard: AEC-Q200; Value: 28
R7-R9 = RMCF0603FT10K0: as R41 on sheet I2C EXPANDER
TP19-TP26 = TestPoint_1: Value: KeySwitch IN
